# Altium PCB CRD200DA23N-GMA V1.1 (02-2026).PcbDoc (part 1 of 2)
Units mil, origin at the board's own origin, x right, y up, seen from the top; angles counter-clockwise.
Board outline 11500 x 10500 mil, 6 copper layers (Top Layer, Layer 1, Layer 2, Layer 3, Layer 4, Bottom Layer), stack 92.199 mil thick; 97 components, 36 nets, 406 pads, 60 vias.
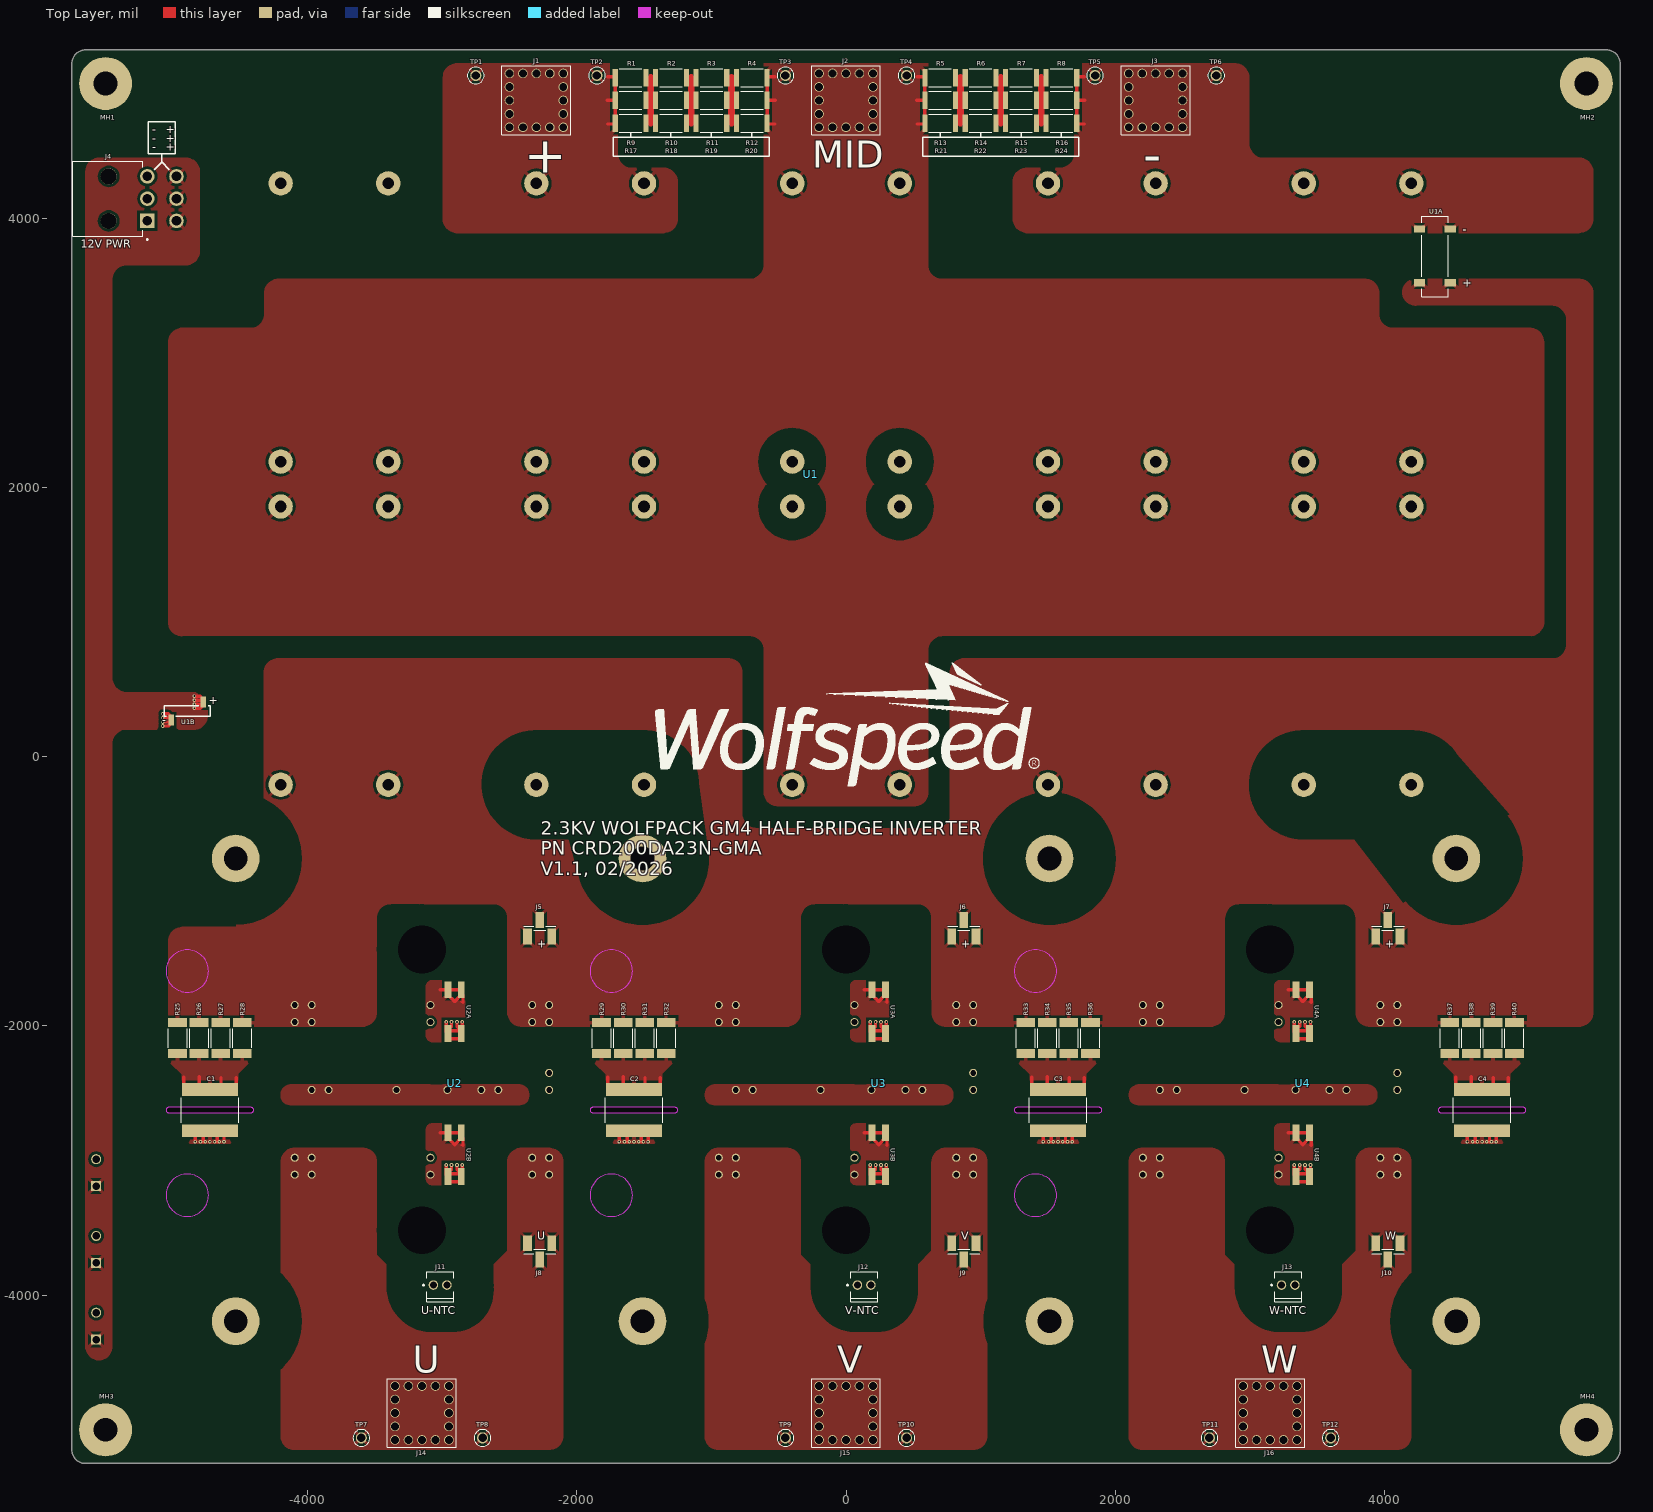
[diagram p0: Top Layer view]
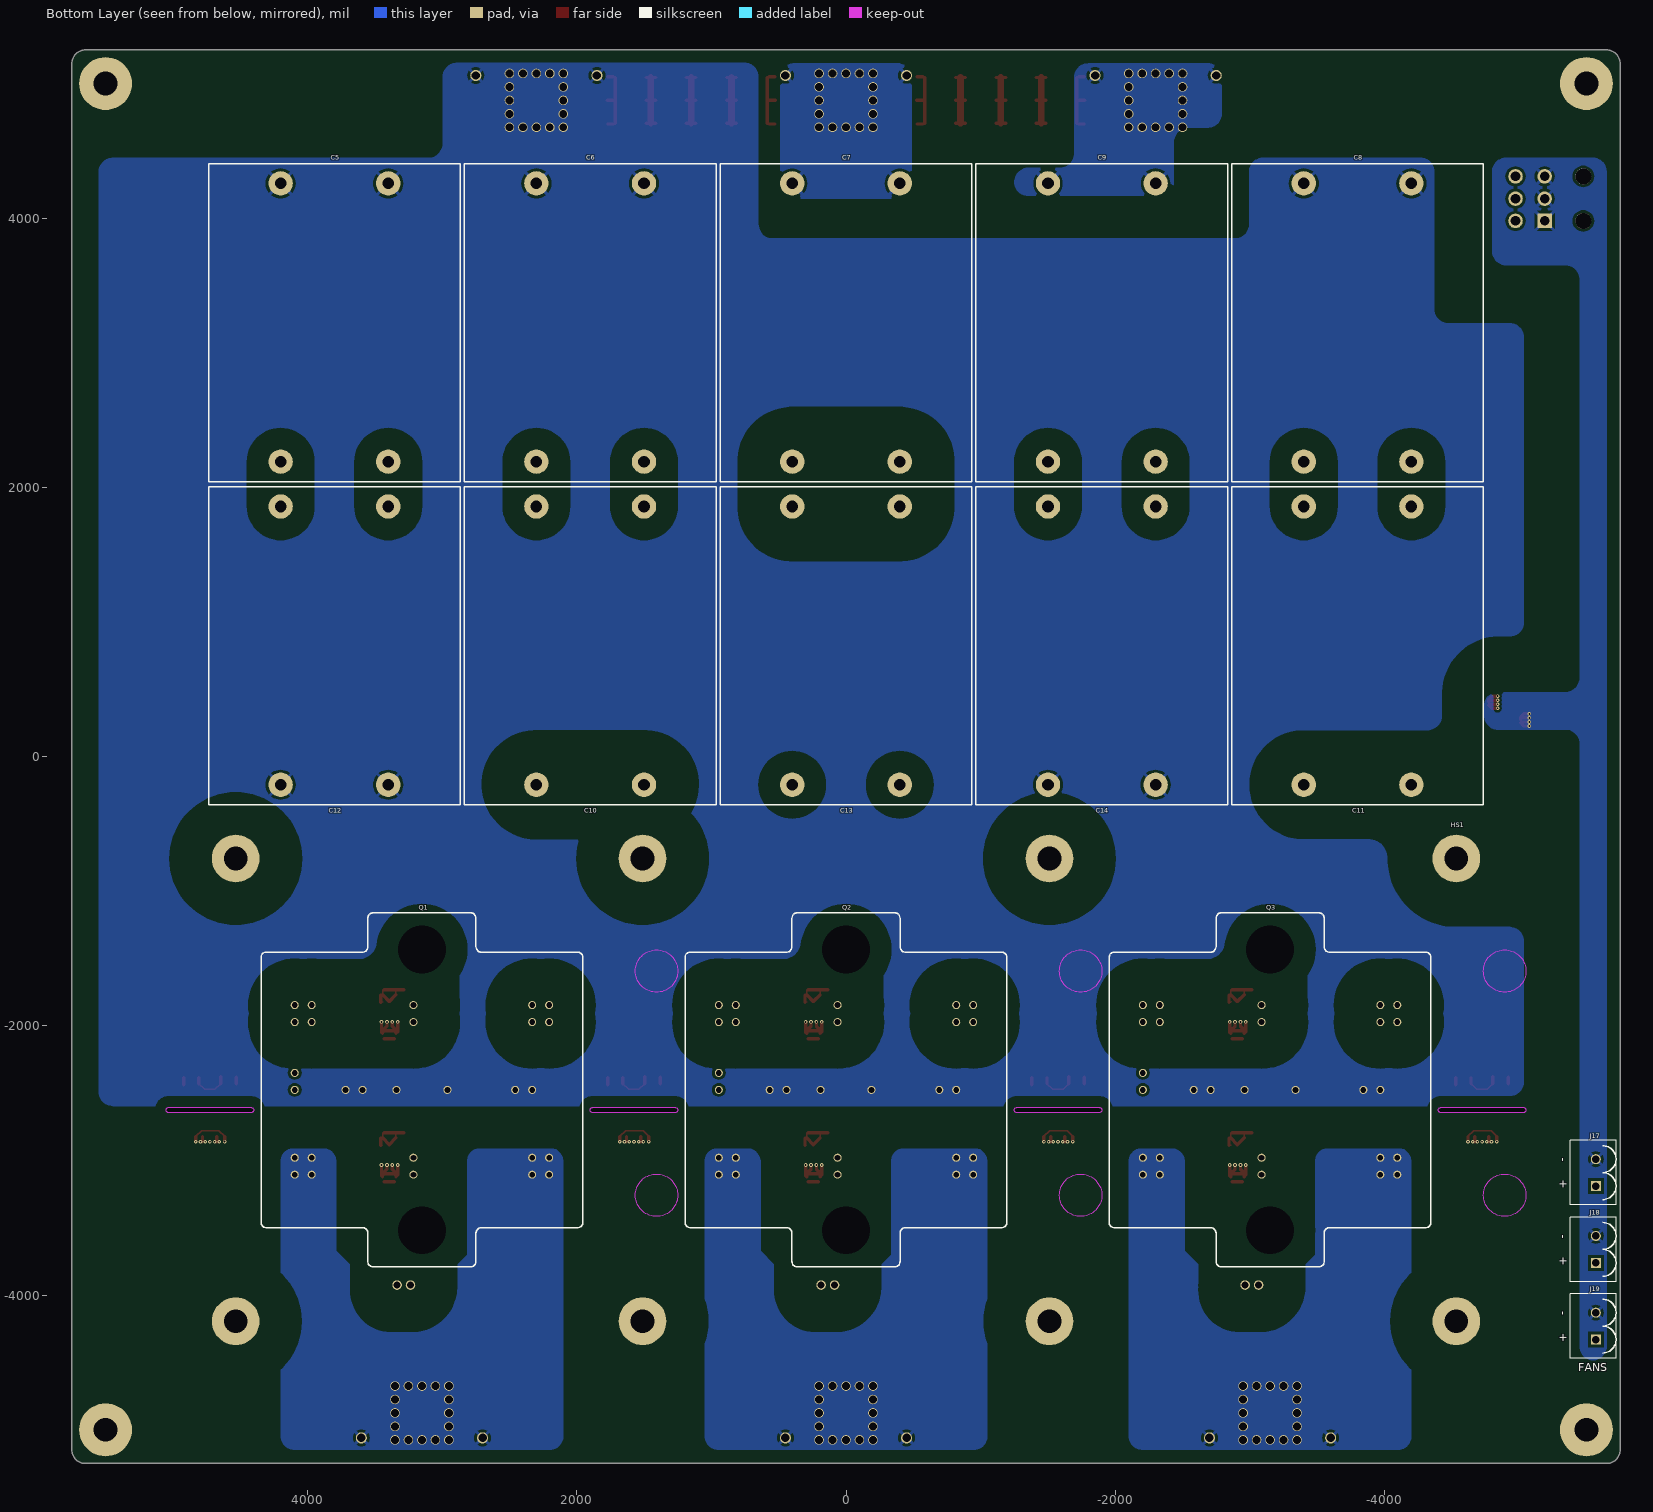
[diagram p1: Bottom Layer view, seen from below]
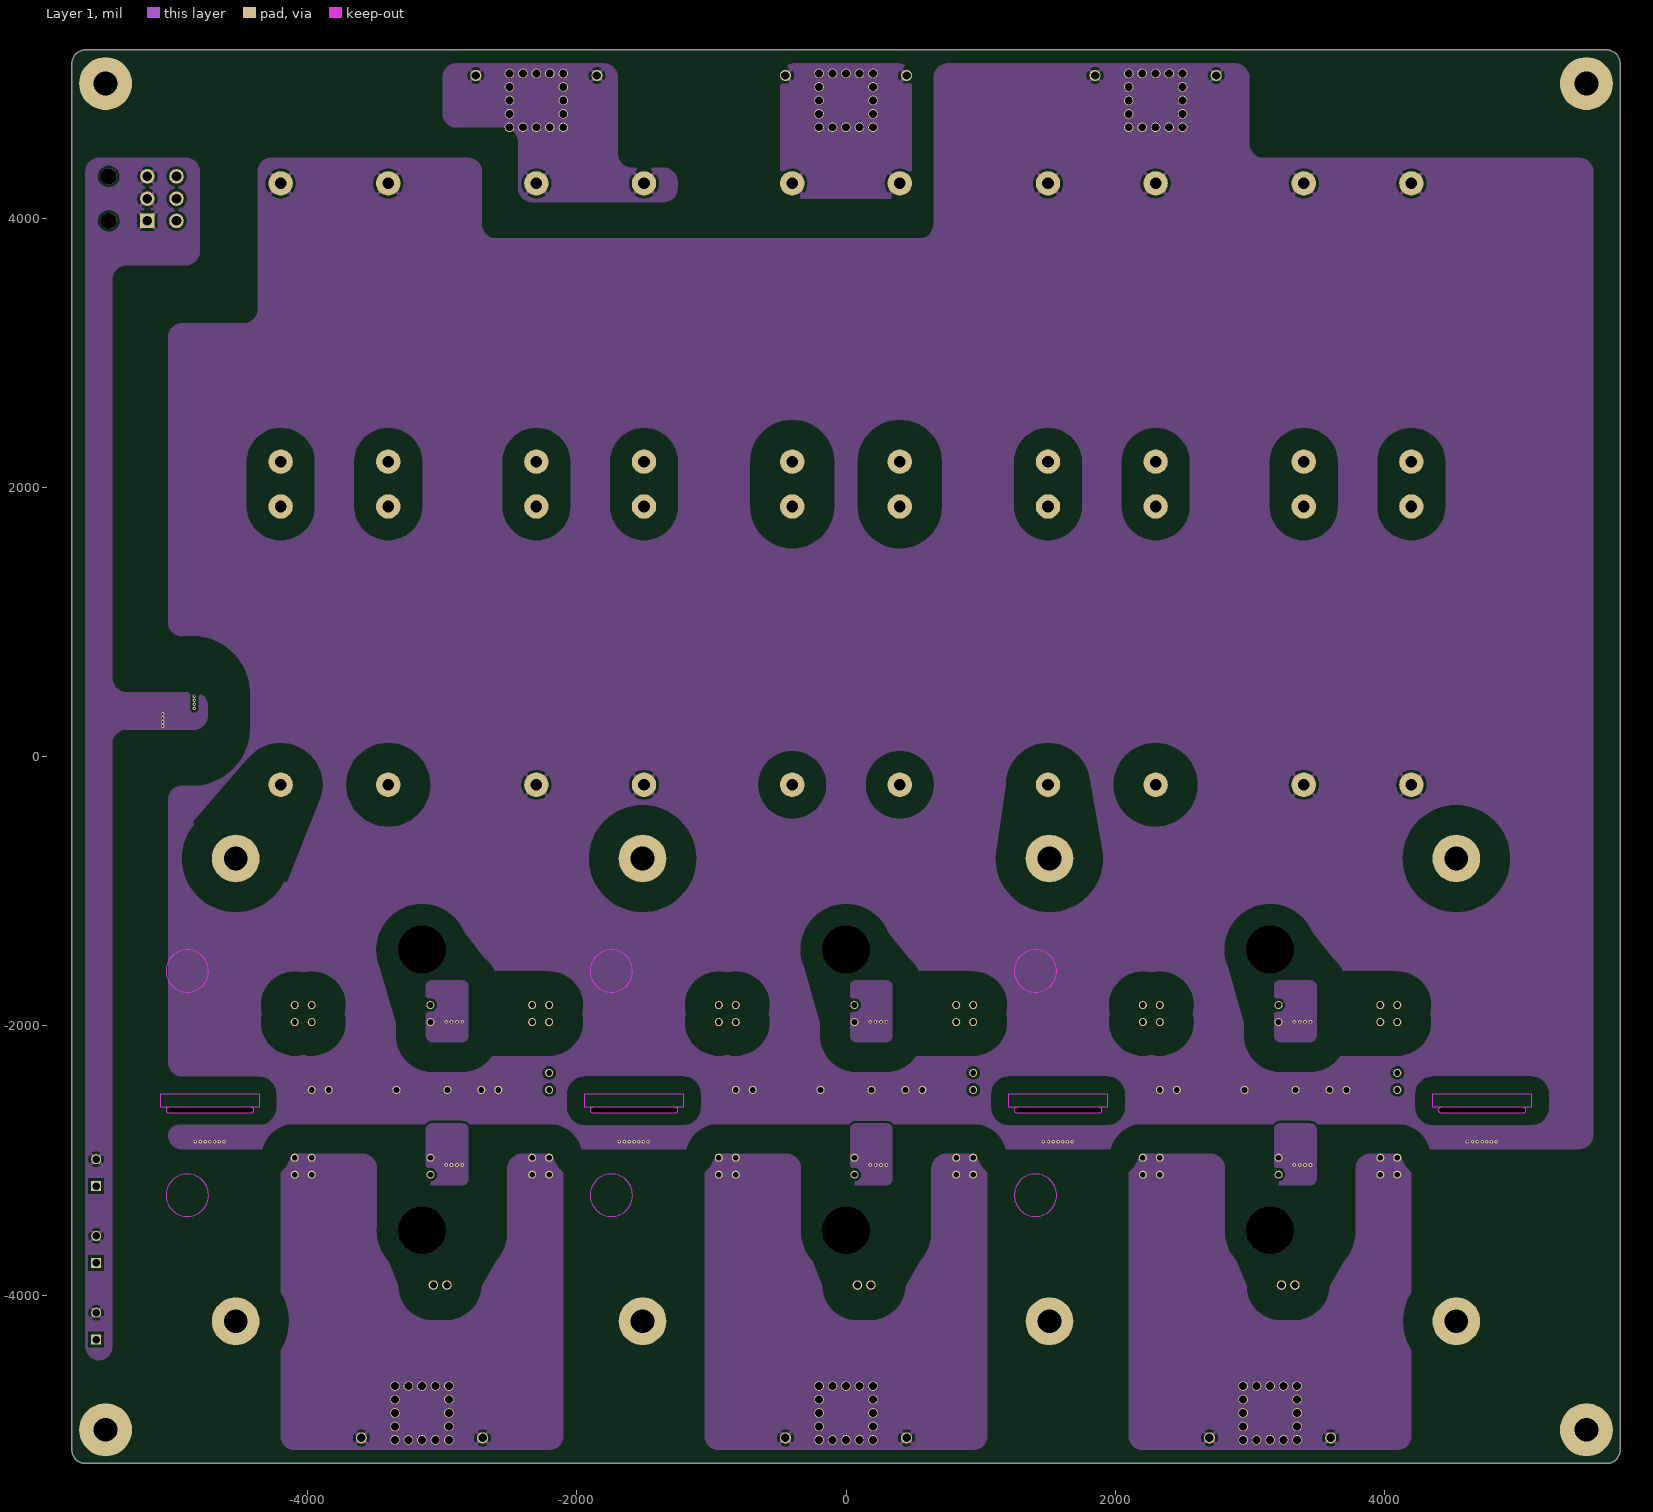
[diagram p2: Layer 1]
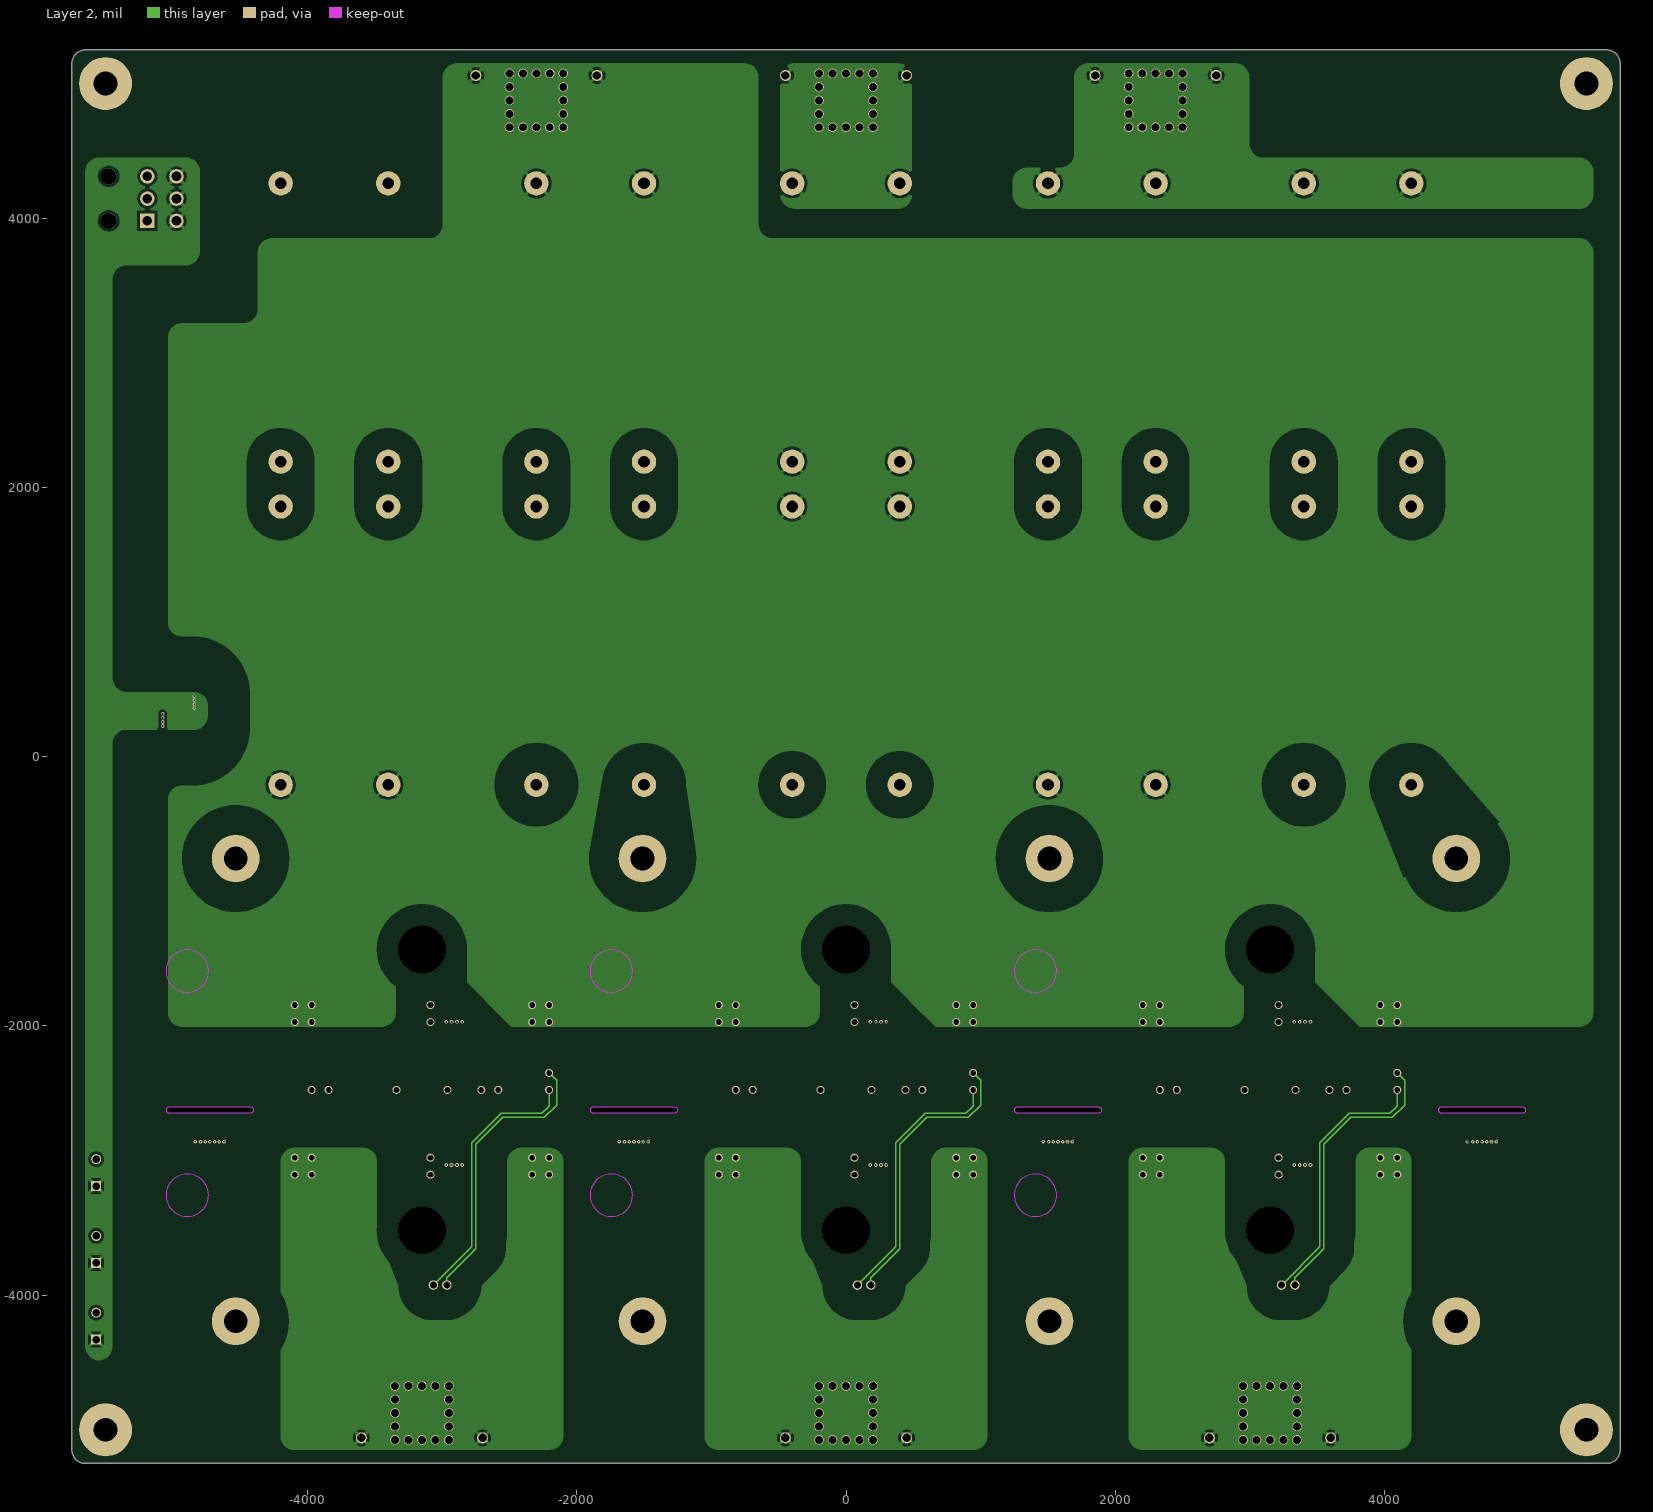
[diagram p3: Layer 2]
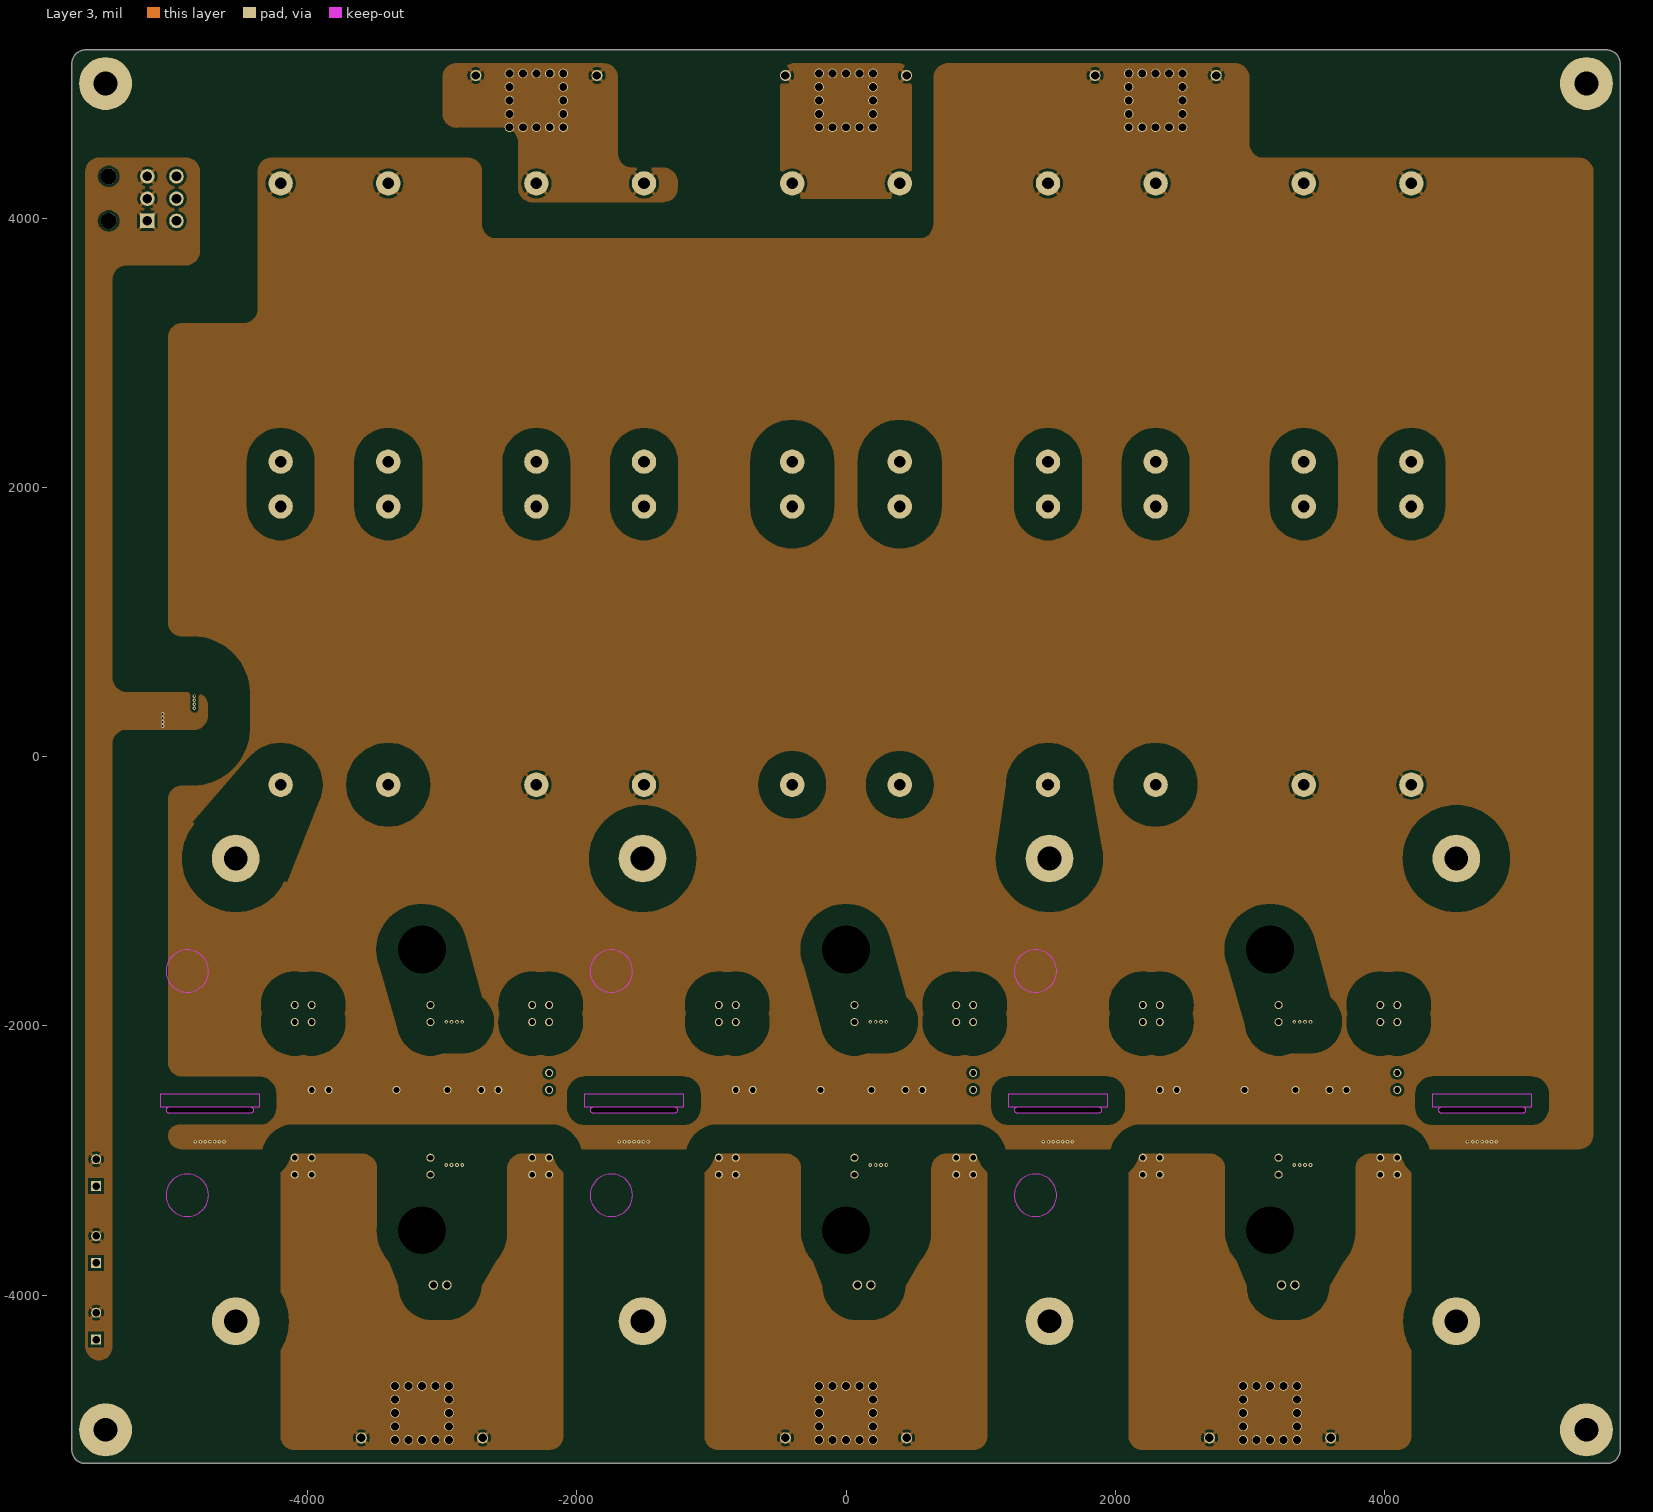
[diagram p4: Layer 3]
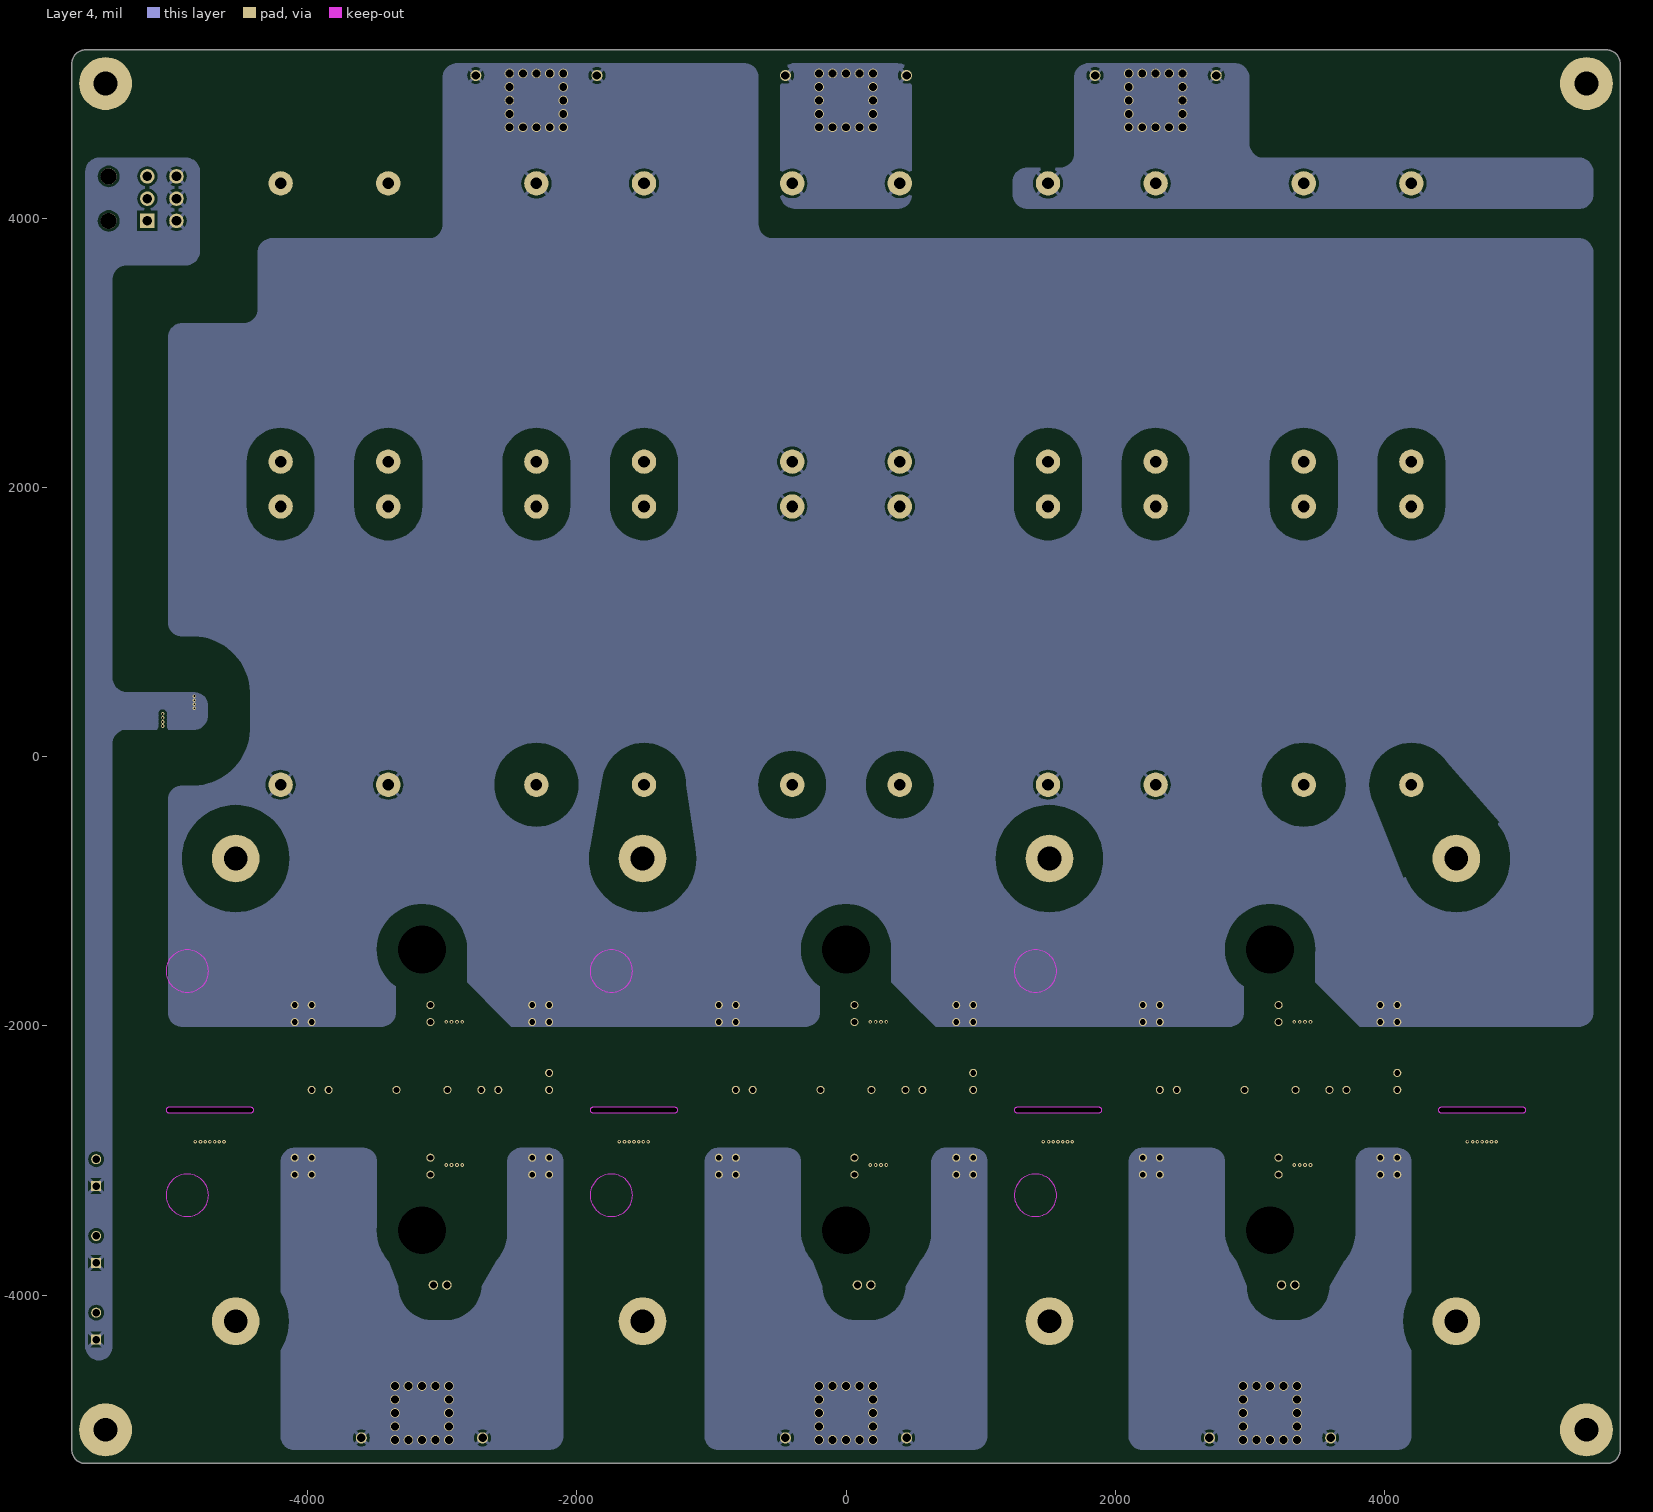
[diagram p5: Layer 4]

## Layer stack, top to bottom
Top Solder: solder mask 0.4, Solder Resist, Dk 3.5
Top Layer: signal copper 5.5118
Dielectric 2: prepreg 2.8, PP-006, Dk 4.1
Layer 1: signal copper 5.5118
Dielectric 3: prepreg 2.8, PP-006, Dk 4.1
Layer 2: signal copper 5.5118
Dielectric 1: dielectric 47.928, FR-4, Dk 4.8
Layer 3: signal copper 5.5118
Dielectric 4: prepreg 2.8, PP-006, Dk 4.1
Layer 4: signal copper 5.5118
Dielectric 5: prepreg 2.8, PP-006, Dk 4.1
Bottom Layer: signal copper 5.5118
Bottom Solder: solder mask 0.4, Solder Resist, Dk 3.5

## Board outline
-5750,-5150 -5750,5150 cw(c-5650,5150) -5650,5250 5650,5250 cw(c5650,5150) 5750,5150 5750,-5150 cw(c5650,-5150) 5650,-5250 -5650,-5250 cw(c-5650,-5150)
cut-out: -5030,-2605 ccw(c-5030,-2625) -5030,-2645 -4420,-2645 ccw(c-4420,-2625) -4420,-2605
cut-out: 4420,-2605 ccw(c4420,-2625) 4420,-2645 5030,-2645 ccw(c5030,-2625) 5030,-2605
cut-out: 1270,-2605 ccw(c1270,-2625) 1270,-2645 1880,-2645 ccw(c1880,-2625) 1880,-2605
cut-out: -1880,-2605 ccw(c-1880,-2625) -1880,-2645 -1270,-2645 ccw(c-1270,-2625) -1270,-2605

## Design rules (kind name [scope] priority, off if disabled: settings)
Clearance "DC+ to DC+" [InNetClass('DC+_CLASS') vs InNetClass('DC+_CLASS')] p1: gap=20 ignorepadtopadclearanceinfootprint=FALSE
Clearance "DC- to DC-" [InNetClass('DC-_CLASS') vs InNetClass('DC-_CLASS')] p2: gap=20 ignorepadtopadclearanceinfootprint=FALSE
Clearance "U to U" [InNetClass('U_CLASS') vs InNetClass('U_CLASS')] p3: gap=20 ignorepadtopadclearanceinfootprint=FALSE
Clearance "V to V" [InNetClass('V_CLASS') vs InNetClass('V_CLASS')] p4: gap=20 ignorepadtopadclearanceinfootprint=FALSE
Clearance "W to W" [InNetClass('W_CLASS') vs InNetClass('W_CLASS')] p5: gap=20 ignorepadtopadclearanceinfootprint=FALSE
Clearance "LV to LV" [InNetClass('LV_CLASS') vs InNetClass('LV_CLASS')] p6: gap=20 ignorepadtopadclearanceinfootprint=TRUE
Clearance "Heat Sink EXT" [OnOutside vs HasFootprint('LA HB 9 100')] p7: gap=315 ignorepadtopadclearanceinfootprint=FALSE
Clearance "Heat Sink INT" [OnMid vs HasFootprint('LA HB 9 100')] p8: gap=220 ignorepadtopadclearanceinfootprint=FALSE
Clearance "LV to Other" [InNetClass('LV_CLASS') vs Not InNetClass('LV_CLASS')] p9: gap=315 ignorepadtopadclearanceinfootprint=FALSE except(20: Arc-Hole Track-Hole SMDPad-Hole THPad-Hole Via-Hole Fill-Hole Poly-Hole Region-Hole Text-Hole)
Clearance "HS Gate-Source Creepage" [InNet('G_UHS') Or InNet('S_UHS') Or InNet('G_VHS') Or InNet('S_VHS') Or InNet('G_WHS') Or InNet('S_WHS') vs Hole] p10: gap=20 ignorepadtopadclearanceinfootprint=FALSE
Clearance MID [InNetClass('MID_CLASS')] p11: gap=160 ignorepadtopadclearanceinfootprint=FALSE
Clearance "SNUB to DC+" [InNetClass('SNUB_CLASS') vs InNetClass('DC+_CLASS')] p12: gap=160 ignorepadtopadclearanceinfootprint=FALSE
Clearance "SNUB to DC-" [InNetClass('SNUB_CLASS') vs InNetClass('DC-_CLASS')] p13: gap=210 ignorepadtopadclearanceinfootprint=FALSE
Clearance Cutout [InNet('DC-') vs IsBoardCutoutRegion] p14: gap=85 ignorepadtopadclearanceinfootprint=FALSE
Clearance Keepout [InNet('DC-') vs IsKeepOut] p15: gap=130 ignorepadtopadclearanceinfootprint=FALSE
Clearance BLD+ [InNetClass('BLD+_CLASS') vs InNetClass('DC+_CLASS') Or InNetClass('MID_CLASS') Or InNetClass('BLD+_CLASS')] p16: gap=160 ignorepadtopadclearanceinfootprint=FALSE
Clearance BLD- [InNetClass('BLD-_CLASS') vs InNetClass('DC-_CLASS') Or InNetClass('MID_CLASS') Or InNetClass('BLD-_CLASS')] p17: gap=160 ignorepadtopadclearanceinfootprint=FALSE
Clearance "External Layers" [InNetClass('All Nets') vs OnOutside] p18: gap=315 ignorepadtopadclearanceinfootprint=TRUE except(160: Arc-Hole Track-Hole SMDPad-Hole THPad-Hole Via-Hole Fill-Hole Poly-Hole Region-Hole Text-Hole)
Clearance "Internal Layers" [InNetClass('All Nets') vs OnMid] p19: gap=220 ignorepadtopadclearanceinfootprint=TRUE except(160: Arc-Hole Track-Hole SMDPad-Hole THPad-Hole Via-Hole Fill-Hole Poly-Hole Region-Hole Text-Hole)
Clearance Default [All] p20: gap=20 ignorepadtopadclearanceinfootprint=FALSE except(160: Arc-Hole Track-Hole SMDPad-Hole THPad-Hole Via-Hole Fill-Hole Poly-Hole Region-Hole Text-Hole)
Height [All] p1: minheight=0 maxheight=4000 prefheight=500
HoleSize [All] p1: absolutevalues=TRUE maxlimit=360 minlimit=1 maxpercent=80.000 minpercent=20.000
PolygonConnect "90Deg Connect" [All vs HasFootprint('FP-RMCF2512-IPC_A') Or HasFootprint('CAPC9501060_270N_KEM')] p1: connectstyle=Relief reliefconductorwidth=25 reliefentries=4 polygonreliefangle="90 Angle" airgapwidth=20
PolygonConnect "Press-Fit Connect" [All vs HasFootprint('7461059') Or HasFootprint('CAB5R0A23GM4_NOHOLE')] p2: connectstyle=Direct reliefconductorwidth=10 reliefentries=4 polygonreliefangle="90 Angle" airgapwidth=10
PolygonConnect [All] p3: thpad.connectstyle=Relief thpad.reliefconductorwidth=25 thpad.reliefentries=4 thpad.polygonreliefangle="45 Angle" thpad.airgapwidth=20 smdpad.connectstyle=Relief smdpad.reliefconductorwidth=25 smdpad.reliefentries=4 smdpad.polygonreliefangle="45 Angle" smdpad.airgapwidth=20 via.connectstyle=Direct via.reliefconductorwidth=25 via.reliefentries=4 via.polygonreliefangle="45 Angle" via.airgapwidth=20
RoutingVias [All] p1: holewidth=28 width=50 viastyle="Through Hole" minholewidth=28 minwidth=50 maxholewidth=28 maxwidth=50
SilkToSolderMaskClearance [IsPad] p1: minsilkscreentomaskgap=7.5 clearancetoexposedcopper=TRUE
SolderMaskExpansion [All] p1: expansion=4 istentingtop=FALSE
SupplyNets "Schematic Supply Nets_1" [InNet('GND')] p1: voltage=0.000
SupplyNets "Schematic Supply Nets" [InNet('+12V')] p2: voltage=0.000
Width [All] p1: maxlimit=100 minlimit=10 preferedwidth=25
27 further rules are at their usual default settings.

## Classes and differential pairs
net class SNUB_CLASS: SNB0 SNB1 SNB2 SNB3
net class BLD-_CLASS: BLD-0 BLD-1 BLD-2
net class BLD+_CLASS: BLD+0 BLD+1 BLD+2
net class LV_CLASS: +12V GND
net class W_CLASS: G_WHS S_WHS W
net class V_CLASS: G_VHS S_VHS V
net class U_CLASS: G_UHS S_UHS U
net class MID_CLASS: MID
net class DC-_CLASS: DC- G_ULS G_VLS G_WLS S_ULS S_VLS S_WLS T1U T1V T1W T2U T2V T2W
net class DC+_CLASS: DC+

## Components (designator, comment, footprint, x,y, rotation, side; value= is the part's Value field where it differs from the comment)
C1 "C3640C153JGGACAUTO" CAPC9501060_270N_KEM -4725,-2625 r270 top value=15nF (schematic designator C12)
C2 "C3640C153JGGACAUTO" CAPC9501060_270N_KEM -1575,-2625 r270 top value=15nF (schematic designator C11)
C3 "C3640C153JGGACAUTO" CAPC9501060_270N_KEM 1575,-2625 r270 top value=15nF (schematic designator C14)
C4 "C3640C153JGGACAUTO" CAPC9501060_270N_KEM 4725,-2625 r270 top value=15nF (schematic designator C13)
C5 "C4AQQEW5650A3BJ" C4AQNEW5650M3BJ 3800,3225 r90 bottom value=65µF (schematic designator C7)
C6 "C4AQQEW5650A3BJ" C4AQNEW5650M3BJ 1900,3225 r90 bottom value=65µF (schematic designator C10)
C7 "C4AQQEW5650A3BJ" C4AQNEW5650M3BJ 0,3225 r90 bottom value=65µF (schematic designator C1)
C8 "C4AQQEW5650A3BJ" C4AQNEW5650M3BJ -3800,3225 r90 bottom value=65µF (schematic designator C5)
C9 "C4AQQEW5650A3BJ" C4AQNEW5650M3BJ -1900,3225 r270 bottom value=65µF (schematic designator C3)
C10 "C4AQQEW5650A3BJ" C4AQNEW5650M3BJ 1900,825 r90 bottom value=65µF (schematic designator C4)
C11 "C4AQQEW5650A3BJ" C4AQNEW5650M3BJ -3800,825 r90 bottom value=65µF (schematic designator C9)
C12 "C4AQQEW5650A3BJ" C4AQNEW5650M3BJ 3800,825 r270 bottom value=65µF (schematic designator C6)
C13 "C4AQQEW5650A3BJ" C4AQNEW5650M3BJ 0,825 r270 bottom value=65µF (schematic designator C2)
C14 "C4AQQEW5650A3BJ" C4AQNEW5650M3BJ -1900,825 r270 bottom value=65µF (schematic designator C8)
HS1 "LA HB 9 100 12" "LA HB 9 100" 0,-2475 r180 bottom value=N/A
J1 "7461059" 7461059 -2300,4875 r0 top value=N/A
J2 "7461059" 7461059 0,4875 r0 top value=N/A (schematic designator J6)
J3 "7461059" 7461059 2300,4875 r0 top value=N/A (schematic designator J5)
J4 "0039301062" FP-39-30-1062-MFG -5485,4145 r270 top value=N/A (schematic designator J16)
J5 "4928" KEYSTONE_4928 -2275,-1275 r180 top value=N/A (schematic designator J10)
J6 "4928" KEYSTONE_4928 875,-1275 r180 top value=N/A (schematic designator J11)
J7 "4928" KEYSTONE_4928 4025,-1275 r180 top value=N/A (schematic designator J12)
J8 "4928" KEYSTONE_4928 -2275,-3675 r0 top value=N/A (schematic designator J13)
J9 "4928" KEYSTONE_4928 875,-3675 r0 top value=N/A (schematic designator J14)
J10 "4928" KEYSTONE_4928 4025,-3675 r0 top value=N/A (schematic designator J15)
J11 "640456-2" TECO-640456-2_V -3015,-3925 r180 top value=N/A (schematic designator J7)
J12 "640456-2" TECO-640456-2_V 135,-3925 r180 top value=N/A (schematic designator J8)
J13 "640456-2" TECO-640456-2_V 3285,-3925 r180 top value=N/A (schematic designator J9)
J14 "7461059" 7461059 -3150,-4875 r0 top value=N/A (schematic designator J2)
J15 "7461059" 7461059 0,-4875 r0 top value=N/A (schematic designator J3)
J16 "7461059" 7461059 3150,-4875 r0 top value=N/A (schematic designator J4)
J17 "1755736" 1755736 -5570,-3090 r90 bottom value=N/A (schematic designator J19)
J18 "1755736" 1755736 -5570,-3660 r90 bottom value=N/A
J19 "1755736" 1755736 -5570,-4230 r90 bottom value=N/A (schematic designator J17)
MH1 "MH_M4_P" MH_M4_P -5500,5000 r0 top value=N/A
MH2 "MH_M4_P" MH_M4_P 5500,5000 r0 top value=N/A
MH3 "MH_M4_P" MH_M4_P -5500,-5000 r0 top value=N/A
MH4 "MH_M4_P" MH_M4_P 5500,-5000 r0 top value=N/A
Q1 "CAB5R0A23GM4T" CAB5R0A23GM4_NOHOLE 3150,-2475 r180 bottom value=N/A (schematic designator Q3)
Q2 "CAB5R0A23GM4T" CAB5R0A23GM4_NOHOLE 0,-2475 r180 bottom locked value=N/A
Q3 "CAB5R0A23GM4T" CAB5R0A23GM4_NOHOLE -3150,-2475 r180 bottom locked value=N/A (schematic designator Q1)
R1 "CRGP2512F220K" FP-CRGP2512-IPC_C -1600,5045 r180 top value=220kΩ
R2 "CRGP2512F220K" FP-CRGP2512-IPC_C -1300,5045 r180 top value=220kΩ (schematic designator R4)
R3 "CRGP2512F220K" FP-CRGP2512-IPC_C -1000,5045 r180 top value=220kΩ (schematic designator R7)
R4 "CRGP2512F220K" FP-CRGP2512-IPC_C -700,5045 r180 top value=220kΩ (schematic designator R10)
R5 "CRGP2512F220K" FP-CRGP2512-IPC_C 700,5045 r180 top value=220kΩ (schematic designator R15)
R6 "CRGP2512F220K" FP-CRGP2512-IPC_C 1000,5045 r180 top value=220kΩ (schematic designator R16)
R7 "CRGP2512F220K" FP-CRGP2512-IPC_C 1300,5045 r180 top value=220kΩ (schematic designator R21)
R8 "CRGP2512F220K" FP-CRGP2512-IPC_C 1600,5045 r180 top value=220kΩ (schematic designator R22)
R9 "CRGP2512F220K" FP-CRGP2512-IPC_C -1600,4875 r180 top value=220kΩ (schematic designator R2)
R10 "CRGP2512F220K" FP-CRGP2512-IPC_C -1300,4875 r180 top value=220kΩ (schematic designator R5)
R11 "CRGP2512F220K" FP-CRGP2512-IPC_C -1000,4875 r180 top value=220kΩ (schematic designator R8)
R12 "CRGP2512F220K" FP-CRGP2512-IPC_C -700,4875 r180 top value=220kΩ (schematic designator R11)
R13 "CRGP2512F220K" FP-CRGP2512-IPC_C 700,4875 r180 top value=220kΩ (schematic designator R14)
R14 "CRGP2512F220K" FP-CRGP2512-IPC_C 1000,4875 r180 top value=220kΩ (schematic designator R17)
R15 "CRGP2512F220K" FP-CRGP2512-IPC_C 1300,4875 r180 top value=220kΩ (schematic designator R19)
R16 "CRGP2512F220K" FP-CRGP2512-IPC_C 1600,4875 r180 top value=220kΩ (schematic designator R23)
R17 "CRGP2512F220K" FP-CRGP2512-IPC_C -1600,4705 r180 top value=220kΩ (schematic designator R3)
R18 "CRGP2512F220K" FP-CRGP2512-IPC_C -1300,4705 r180 top value=220kΩ (schematic designator R6)
R19 "CRGP2512F220K" FP-CRGP2512-IPC_C -1000,4705 r180 top value=220kΩ (schematic designator R9)
R20 "CRGP2512F220K" FP-CRGP2512-IPC_C -700,4705 r180 top value=220kΩ (schematic designator R12)
R21 "CRGP2512F220K" FP-CRGP2512-IPC_C 700,4705 r180 top value=220kΩ (schematic designator R13)
R22 "CRGP2512F220K" FP-CRGP2512-IPC_C 1000,4705 r180 top value=220kΩ (schematic designator R18)
R23 "CRGP2512F220K" FP-CRGP2512-IPC_C 1300,4705 r180 top value=220kΩ (schematic designator R20)
R24 "CRGP2512F220K" FP-CRGP2512-IPC_C 1600,4705 r180 top value=220kΩ
R25 "CRCW251210R0FKEGHP" FP-RMCF2512-IPC_A -4965,-2090 r90 top value=10Ω (schematic designator R29)
R26 "CRCW251210R0FKEGHP" FP-RMCF2512-IPC_A -4805,-2090 r90 top value=10Ω (schematic designator R30)
R27 "CRCW251210R0FKEGHP" FP-RMCF2512-IPC_A -4645,-2090 r90 top value=10Ω (schematic designator R31)
R28 "CRCW251210R0FKEGHP" FP-RMCF2512-IPC_A -4485,-2090 r90 top value=10Ω (schematic designator R32)
R29 "CRCW251210R0FKEGHP" FP-RMCF2512-IPC_A -1815,-2090 r90 top value=10Ω (schematic designator R25)
R30 "CRCW251210R0FKEGHP" FP-RMCF2512-IPC_A -1655,-2090 r90 top value=10Ω (schematic designator R26)
R31 "CRCW251210R0FKEGHP" FP-RMCF2512-IPC_A -1495,-2090 r90 top value=10Ω (schematic designator R27)
R32 "CRCW251210R0FKEGHP" FP-RMCF2512-IPC_A -1335,-2090 r90 top value=10Ω (schematic designator R28)
R33 "CRCW251210R0FKEGHP" FP-RMCF2512-IPC_A 1335,-2090 r90 top value=10Ω (schematic designator R37)
R34 "CRCW251210R0FKEGHP" FP-RMCF2512-IPC_A 1495,-2090 r90 top value=10Ω (schematic designator R38)
R35 "CRCW251210R0FKEGHP" FP-RMCF2512-IPC_A 1655,-2090 r90 top value=10Ω (schematic designator R39)
R36 "CRCW251210R0FKEGHP" FP-RMCF2512-IPC_A 1815,-2090 r90 top value=10Ω (schematic designator R40)
R37 "CRCW251210R0FKEGHP" FP-RMCF2512-IPC_A 4485,-2090 r90 top value=10Ω (schematic designator R33)
R38 "CRCW251210R0FKEGHP" FP-RMCF2512-IPC_A 4645,-2090 r90 top value=10Ω (schematic designator R34)
R39 "CRCW251210R0FKEGHP" FP-RMCF2512-IPC_A 4805,-2090 r90 top value=10Ω (schematic designator R35)
R40 "CRCW251210R0FKEGHP" FP-RMCF2512-IPC_A 4965,-2090 r90 top value=10Ω (schematic designator R36)
TP1 "5010" KSTN-5010_V -2750,5060 r0 top value=RED (schematic designator TP2)
TP2 "5010" KSTN-5010_V -1850,5060 r0 top value=RED (schematic designator TP1)
TP3 "5012" KSTN-5012_V -450,5060 r0 top value=WHITE (schematic designator TP5)
TP4 "5012" KSTN-5012_V 450,5060 r0 top value=WHITE (schematic designator TP6)
TP5 "5011" KSTN-5011_V 1850,5060 r0 top value=BLACK (schematic designator TP3)
TP6 "5011" KSTN-5011_V 2750,5060 r0 top value=BLACK (schematic designator TP4)
TP7 "5014" KSTN-5014_V -3600,-5060 r0 top value=YELLOW
TP8 "5014" KSTN-5014_V -2700,-5060 r0 top value=YELLOW
TP9 "5014" KSTN-5014_V -450,-5060 r0 top value=YELLOW
TP10 "5014" KSTN-5014_V 450,-5060 r0 top value=YELLOW
TP11 "5014" KSTN-5014_V 2700,-5060 r0 top value=YELLOW
TP12 "5014" KSTN-5014_V 3600,-5060 r0 top value=YELLOW
U1 "XM Controller" "XM CONTROLLER" 0,2200 r0 top value=N/A (schematic designator U4)
U2 "CGD1700HB2M-UNA" CGD1700HB2P-UNA_NOHOLE -3875,-2425 r0 top locked value=N/A (schematic designator U1)
U3 "CGD1700HB2M-UNA" CGD1700HB2P-UNA_NOHOLE -725,-2425 r0 top locked value=N/A (schematic designator U2)
U4 "CGD1700HB2M-UNA" CGD1700HB2P-UNA_NOHOLE 2425,-2425 r0 top value=N/A (schematic designator U3)

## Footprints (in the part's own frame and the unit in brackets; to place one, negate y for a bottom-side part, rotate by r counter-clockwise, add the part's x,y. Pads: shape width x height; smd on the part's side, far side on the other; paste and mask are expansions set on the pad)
1755736 [mm] "THD, 2-Leads, Body 12.16x8.6mm, Pitch 5.08mm"
  rect 1.9x1.9 hole 1.4: 1(-2.54,0)
  round 1.9 hole 1.4: 2(2.54,0)
  silkscreen extent -6.08,-3.81 6.08,4.79, body extent -6.08,-3.8 6.16,4.87, height 12
7461059 [mm] "M6, thr 13.5mm"
  round 1.8 hole 1.475: 1(-5.08,-5.08) 1(-5.08,-2.54) 1(-5.08,0) 1(-5.08,2.54) 1(-5.08,5.08) 1(-2.54,-5.08) 1(-2.54,5.08) 1(0,-5.08) 1(0,5.08) 1(2.54,-5.08) 1(2.54,5.08) 1(5.08,-5.08) 1(5.08,-2.54) 1(5.08,0) 1(5.08,2.54) 1(5.08,5.08)
  silkscreen extent -6.5,-6.5 6.5,6.5, body extent -6.5,-6.5 6.5,6.5, height 13.5
C4AQNEW5650M3BJ [mm]
  round 4.6 hole 2.2: 1A(-26.25,10.15) 1B(-26.25,-10.15) 2A(26.25,10.15) 2B(26.25,-10.15)
  silkscreen extent -30,-23.75 30,23.75, body extent -29.15,-22.81 29.15,22.7, height 65.3
CAB5R0A23GM4_NOHOLE [mm] "Wolfpack GM Half-Bridge 2.3kV footprint"
  round 1.524 hole 1.09: AC_1(-24,-12.8) AC_2(-24,-16) AC_3(-20.8,-12.8) AC_4(-20.8,-16) AC_5(20.8,-12.8) AC_6(20.8,-16) AC_7(24,-12.8) AC_8(24,-16) DC+_1(-24,16) DC+_2(-24,12.8) DC+_3(-20.8,16) DC+_4(-20.8,12.8) DC+_5(20.8,16) DC+_6(20.8,12.8) DC+_7(24,16) DC+_8(24,12.8) DC-_1(20.8,0) DC-_2(17.6,0) DC-_3(-4.8,0) DC-_4(4.8,0) DC-_5(-11.2,0) DC-_6(-14.4,0) G1(-1.6,16) G2(-1.6,-16) S1(-1.6,12.8) S2(-1.6,-12.8) T1(-24,3.2) T2(-24,0)
  round 0.1 hole 9 unplated: ""(0,-26.5) ""(0,26.5)
  silkscreen extent -30.35,-33.4 30.35,33.4, body extent -28.35,-31.39 28.35,31.41, height 17.35
CAPC9501060_270N_KEM [mil]
  rect 95.5x417.32 smd paste+0 mask+0: 1(-153.26,0) 2(153.26,0)
  silkscreen extent -93,-214 93,214, body extent -187,-209 187,209, height 106
CGD1700HB2P-UNA_NOHOLE [mil] "Wolfpack FM/GM Gate Driver"
  rect 50x125 smd: 1A(917.84,369) 1B(917.84,-694) 2A(917.84,694) 2B(917.84,-369) 3A(1017.84,369) 3B(1017.84,-694) 4A(1017.84,694) 4B(1017.84,-369)
  Multi-Layer keep-out region: -1017.84,990 -1017.84,990 -1031.56,989.4 -1045.18,987.61 -1058.59,984.63 -1071.7,980.5 -1084.39,975.25 -1096.57,968.9 -1108.16,961.52 -1119.06,953.16 -1129.19,943.88 -1138.47,933.75 -1146.84,922.85 -1154.22,911.26 -1160.56,899.07 -1165.82,886.38 -1169.95,873.28 -1172.92,859.87 -1174.72,846.25 -1175.32,832.52 -1174.72,818.79 -1172.92,805.17 -1169.95,791.76 -1165.82,778.66 -1160.56,765.97 -1154.22,753.78 -1146.84,742.19 -1138.47,731.29 -1129.19,721.16 -1119.06,711.88 -1108.16,703.52 -1096.57,696.14 -1084.39,689.79 -1071.7,684.54 -1058.59,680.41 -1045.18,677.43 -1031.56,675.64 -1017.84,675.04 -1017.84,675.04 -1004.11,675.64 -990.49,677.43 -977.08,680.41 -963.97,684.54 -951.28,689.79 -939.09,696.14 -927.51,703.52 -916.61,711.88 -906.48,721.16 -897.2,731.29 -888.83,742.19 -881.45,753.78 -875.11,765.97 -869.85,778.66 -865.72,791.76 -862.75,805.17 -860.95,818.79 -860.36,832.52 -860.95,846.25 -862.75,859.87 -865.72,873.28 -869.85,886.38 -875.11,899.07 -881.45,911.26 -888.83,922.85 -897.2,933.75 -906.48,943.88 -916.61,953.16 -927.51,961.52 -939.09,968.9 -951.28,975.25 -963.97,980.5 -977.08,984.63 -990.49,987.61 -1004.11,989.4 -1017.84,990
  Multi-Layer keep-out region: -1017.84,-675.04 -1017.84,-675.04 -1031.56,-675.64 -1045.18,-677.43 -1058.59,-680.41 -1071.7,-684.54 -1084.39,-689.79 -1096.57,-696.14 -1108.16,-703.52 -1119.06,-711.88 -1129.19,-721.16 -1138.47,-731.29 -1146.84,-742.19 -1154.22,-753.78 -1160.56,-765.97 -1165.82,-778.66 -1169.95,-791.76 -1172.92,-805.17 -1174.72,-818.79 -1175.32,-832.52 -1174.72,-846.25 -1172.92,-859.87 -1169.95,-873.28 -1165.82,-886.38 -1160.56,-899.07 -1154.22,-911.26 -1146.84,-922.85 -1138.47,-933.75 -1129.19,-943.88 -1119.06,-953.16 -1108.16,-961.52 -1096.57,-968.9 -1084.39,-975.25 -1071.7,-980.5 -1058.59,-984.63 -1045.18,-987.61 -1031.56,-989.4 -1017.84,-990 -1017.84,-990 -1004.11,-989.4 -990.49,-987.61 -977.08,-984.63 -963.97,-980.5 -951.28,-975.25 -939.09,-968.9 -927.51,-961.52 -916.61,-953.16 -906.48,-943.88 -897.2,-933.75 -888.83,-922.85 -881.45,-911.26 -875.11,-899.07 -869.85,-886.38 -865.72,-873.28 -862.75,-859.87 -860.95,-846.25 -860.36,-832.52 -860.95,-818.79 -862.75,-805.17 -865.72,-791.76 -869.85,-778.66 -875.11,-765.97 -881.45,-753.78 -888.83,-742.19 -897.2,-731.29 -906.48,-721.16 -916.61,-711.88 -927.51,-703.52 -939.09,-696.14 -951.28,-689.79 -963.97,-684.54 -977.08,-680.41 -990.49,-677.43 -1004.11,-675.64 -1017.84,-675.04
  body extent -1200,-1291 1179,1000, height 1202
FP-39-30-1062-MFG [mm]
  rect 2.75x2.75 hole 1.8 paste-2539.97 mask+0: 1(4.2,7.5)
  round 2.75 hole 1.8 paste-2539.97 mask+0: 2(0,7.5) 3(-4.2,7.5) 4(4.2,13) 5(0,13) 6(-4.2,13)
  round 3 hole 3 unplated paste-2539.97 mask+0: ""(-4.2,0.2) ""(4.2,0.2)
  silkscreen extent -7.09,-6.59 7.81,7.63, body extent -7.19,-6.69 7.19,14.48, height 0.25
FP-CRGP2512-IPC_C [mil]
  rect 37.72x130.17 smd paste+0 mask+0: 1(-114.25,0) 2(114.25,0)
  silkscreen extent -84,-67 84,67, body extent -137,-71 137,71, height 10
FP-RMCF2512-IPC_A [mil]
  rect 67.1x139.96 smd paste+0 mask+0: 1(-116.18,0) 2(116.18,0)
  silkscreen extent -71,-70 71,70, body extent -169,-90 169,90, height 10
KEYSTONE_4928 [mm]
  rect 1.65x3 smd: 1(2.285,1.55) 2(0,-1.55) 3(-2.285,1.55)
  silkscreen extent -3.05,-0.41 3.05,0.41, body extent -3.05,-2.92 3.05,2.92, height 10.52
KSTN-5010_V [mm] "Test Point, Dia 3.17mm"
  round 2.1 hole 1.6: 1(0,0)
  silkscreen extent -1.59,-1.58 1.59,1.58, body extent -1.59,-1.59 1.59,1.59, height 8.13
KSTN-5011_V [mm] "Test Point, Dia 3.17mm"
  round 2.1 hole 1.6: 1(0,0)
  silkscreen extent -1.59,-1.58 1.59,1.58, body extent -1.59,-1.59 1.59,1.59, height 8.13
KSTN-5012_V [mm] "Test Point, Dia 3.17mm"
  round 2.1 hole 1.6: 1(0,0)
  silkscreen extent -1.59,-1.58 1.59,1.58, body extent -1.59,-1.59 1.59,1.59, height 8.13
KSTN-5014_V [mm] "Test Point, Dia 3.17mm"
  round 2.1 hole 1.6: 1(0,0)
  silkscreen extent -1.59,-1.58 1.59,1.58, body extent -1.59,-1.59 1.59,1.59, height 8.13
"LA HB 9 100" [mm]
  round 9 hole 4.5: 1(115.15,43.65) 2(38.38,43.65) 3(-38.38,43.65) 4(-115.15,43.65) 5(-115.15,-43.65) 6(-38.38,-43.65) 7(38.38,-43.65) 8(115.15,-43.65)
  body extent -121.25,-88.53 121.75,49.48, height 2.75
MH_M4_P [mm] "M4 plated mounting hole"
  round 10 hole 4.5: 1(0,0)
  body extent -4.62,-4 4.62,4, height 15
TECO-640456-2_V [mm] "HDR, 2-Leads, Body 5.715x5.08mm, Pitch 2.54mm"
  round 1.8 hole 1.3: 1(1.27,0) 2(-1.27,0)
  silkscreen extent -2.54,-2.54 3.26,3.18, body extent -2.54,-2.67 2.54,3.17, height 10.09
"XM CONTROLLER" [mm]
  rect 2.16x1.4 smd: 1(108.205,43.688) 2(114.045,43.688) 5(108.205,33.528) 6(114.045,33.528)
  rect 1.016x2.085 smd: 11(-127.282,-48.921) 14(-121.282,-45.567)
  silkscreen extent -128.6,-48.26 113.66,46.11, body extent -141.04,-55.2 135,50.8, height 24.54

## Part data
C1 C2 C3 C4: "CAP CER 0.015UF 2KV C0G/NP0 3640", Case/Package=3640, Manufacturer=KEMET, Voltage=2kV
C5 C6 C7 C8 C9 C10 C11 C12 C13 C14: "CAP FILM 65UF 5% 1.1KVDC RAD", Case/Package=RADIAL, Manufacturer=KEMET, Voltage=1.1kV
HS1: "HEATSINK EXTRUSION 100MM", Case/Package=N/A, Manufacturer=FISCHER
J1 J2 J3 J14 J15 J16: "TERM REDCUBE M6 16PIN PCB", Case/Package=N/A, Current Rating=240A, Manufacturer=WURTH, Max Operating Temperature=150°C, Min Operating Temperature=-55°C
J4: "CONN HEADER R/A 6POS 4.2MM", Case/Package=N/A, Manufacturer=MOLEX
J5 J6 J7 J8 J9 J10: "QUICK FIT TERMINAL .240\"", Case/Package=N/A, Manufacturer=KEYSTONE
J11 J12 J13: library part CMP-2000-05417-1, "CONN HEADER VERT 2POS 2.54MM", Case/Package=N/A, Color=White, Current, Rating="5 /  / A", Flammability Rating=UL94V-0, Manufacturer=TE, Temperature, Operating="-55to+105 /  / degC", Voltage, Rating="250 /  / V"
J17 J18 J19: "TERM BLOCK HDR 2POS VERT 5.08MM", Case/Package=N/A, Colour=Green, Manufacturer="PHOENIX CONTACT", Supplier Part Number 1=1896199
MH1 MH2 MH3 MH4: "PLASTIC SPACER STUD METRIC THREA", Case/Package=N/A, Manufacturer=WURTH, Manufacturer Part Number=971500485
Q1 Q2 Q3: "MOSFET 2N-CH 2300V 200A", Case/Package=GM, Manufacturer=WOLFSPEED
R1 R2 R3 R4 R5 R6 R7 R8 R9 R10 R11 R12 R13 R14 R15 R16 R17 R18 R19 R20 R21 R22 R23 R24: "RES 220K OHM 1% 2W 2512", Ambient Temperature Range High=+70°C, Case/Package=2512, Manufacturer=TE, Power Rating=2W, Resistance=220kΩ, Temperature="-55°C to +155°C", Temperature Coefficient=±100ppm/°C, Temperature Range High=+155°C, Temperature Range Low=-55°C, Tolerance=0.01, Voltage Rating=500V
R25 R26 R27 R28 R29 R30 R31 R32 R33 R34 R35 R36 R37 R38 R39 R40: "RES SMD 10 OHM 1% 1.5W 2512", Case/Package=2512, Manufacturer="VISHAY DALE", Power=1.5W
TP1 TP2: library part CMP-1672-00002-4, "PC TEST POINT MULTIPURPOSE RED", Case/Package=N/A, Colour=Red, Manufacturer=KEYSTONE, Package Quantity=100
TP3 TP4: library part CMP-1672-00004-4, "PC TEST POINT MULTIPURPOSE WHITE", Case/Package=N/A, Manufacturer=KEYSTONE, Package Quantity=100
TP5 TP6: library part CMP-1672-00003-4, "PC TEST POINT MULTIPURPOSE BLACK", Case/Package=N/A, Colour=Black, Manufacturer=KEYSTONE, Package Quantity=100
TP7 TP8 TP9 TP10 TP11 TP12: library part CMP-1672-00006-4, "PC TEST POINT MULTIPURPOSE YELLOW", Case/Package=N/A, Manufacturer=KEYSTONE, Package Quantity=100
U1: "CTRL BRD - XM3 EVAL BRD", Case/Package=N/A, Manufacturer=WOLFSPEED, Manufacturer Part Number=CRD300DA12E-XM3-CTRL
U2 U3 U4: "IC GATE DRVR HALF-BRIDGE MODULE", Case/Package=N/A, Manufacturer=WOLFSPEED

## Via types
v1: diameter 27, hole 13, Top Layer to Bottom Layer, tented both sides, 60 vias

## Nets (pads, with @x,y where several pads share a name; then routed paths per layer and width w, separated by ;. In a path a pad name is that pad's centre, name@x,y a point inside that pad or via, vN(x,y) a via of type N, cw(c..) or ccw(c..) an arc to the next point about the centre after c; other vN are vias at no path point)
+12V: J4.4 J4.5 J4.6 J17.1 J18.1 J19.1 U1.14 | length 285.5
  Top Layer w25: v1(-4840,360) -4797.82,360 U1.14@-4774.89,382.93 ; v1(-4840,390) U1.14@-4782.39,390 ; v1(-4840,420) U1.14@-4782.39,420 ; v1(-4840,450) -4797.82,450 -4774.89,427.07 U1.14@-4774.89,406.02
BLD+0: R1.1 R2.2 R9.1 R10.2 R17.1 R18.2 | length 554.5
  Top Layer w25: R17.1@-1485.75,4705 -1450,4705 R18.2@-1414.25,4705 ; R9.1@-1485.75,4875 -1450,4875 R10.2@-1414.25,4875 ; R1.1@-1485.75,5045 -1450,5045 R2.2@-1414.25,5045
  Top Layer w50: -1450,4705 -1450,4875 -1450,5045
BLD+1: R2.1 R3.2 R10.1 R11.2 R18.1 R19.2 | length 554.5
  Top Layer w25: R18.1@-1185.75,4705 -1150,4705 R19.2@-1114.25,4705 ; R10.1@-1185.75,4875 -1150,4875 R11.2@-1114.25,4875 ; R2.1@-1185.75,5045 -1150,5045 R3.2@-1114.25,5045
  Top Layer w50: -1150,4705 -1150,4875 -1150,5045
BLD+2: R3.1 R4.2 R11.1 R12.2 R19.1 R20.2 | length 554.5
  Top Layer w25: R19.1@-885.75,4705 -850,4705 R20.2@-814.25,4705 ; R11.1@-885.75,4875 -850,4875 R12.2@-814.25,4875 ; R3.1@-885.75,5045 -850,5045 R4.2@-814.25,5045
  Top Layer w50: -850,4705 -850,4875 -850,5045
BLD-0: R5.1 R6.2 R13.1 R14.2 R21.1 R22.2 | length 554.5
  Top Layer w25: R21.1@814.25,4705 850,4705 R22.2@885.75,4705 ; R13.1@814.25,4875 850,4875 R14.2@885.75,4875 ; R5.1@814.25,5045 850,5045 R6.2@885.75,5045
  Top Layer w50: 850,4705 850,4875 850,5045
BLD-1: R6.1 R7.2 R14.1 R15.2 R22.1 R23.2 | length 554.5
  Top Layer w25: R22.1@1114.25,4705 1150,4705 R23.2@1185.75,4705 ; R14.1@1114.25,4875 1150,4875 R15.2@1185.75,4875 ; R6.1@1114.25,5045 1150,5045 R7.2@1185.75,5045
  Top Layer w50: 1150,4705 1150,4875 1150,5045
BLD-2: R7.1 R8.2 R15.1 R16.2 R23.1 R24.2 | length 554.5
  Top Layer w25: R23.1@1414.25,4705 1450,4705 R24.2@1485.75,4705 ; R15.1@1414.25,4875 1450,4875 R16.2@1485.75,4875 ; R7.1@1414.25,5045 1450,5045 R8.2@1485.75,5045
  Top Layer w50: 1450,4705 1450,4875 1450,5045
DC+: C7.1A C7.1B C9.1A C9.1B C10.1A C10.1B C11.1A C11.1B C13.1A C13.1B J1.1 J5.1 J5.2 J5.3 J6.1 J6.2 J6.3 J7.1 J7.2 J7.3 Q1.DC+_1 Q1.DC+_2 Q1.DC+_3 Q1.DC+_4 Q1.DC+_5 Q1.DC+_6 Q1.DC+_7 Q1.DC+_8 Q2.DC+_1 Q2.DC+_2 Q2.DC+_3 Q2.DC+_4 Q2.DC+_5 Q2.DC+_6 Q2.DC+_7 Q2.DC+_8 Q3.DC+_1 Q3.DC+_2 Q3.DC+_3 Q3.DC+_4 Q3.DC+_5 Q3.DC+_6 Q3.DC+_7 Q3.DC+_8 R1.2 R9.2 R17.2 R25.2 R26.2 R27.2 R28.2 R29.2 R30.2 R31.2 R32.2 R33.2 R34.2 R35.2 R36.2 R37.2 R38.2 R39.2 R40.2 TP1.1 TP2.1 U1.5 U1.6 | length 514
  Top Layer w10: R17.2@-1728.11,4700 R17.2@-1714.25,4705 ; R1.2@-1728.11,5050 R1.2@-1714.25,5045
  Top Layer w25: -1775,4875 R9.2@-1714.25,4875 ; -1770,4700 R17.2@-1728.11,4700 ; -1770,5050 R1.2@-1728.11,5050 ; R17.2@-1714.25,4705 R9.2@-1714.25,4875 ; R1.2@-1714.25,5045 R9.2@-1714.25,4875
DC-: C1.2 C2.2 C3.2 C4.2 C5.2A C5.2B C6.2A C6.2B C8.2A C8.2B C12.2A C12.2B C14.2A C14.2B J3.1 Q1.DC-_1 Q1.DC-_2 Q1.DC-_3 Q1.DC-_4 Q1.DC-_5 Q1.DC-_6 Q2.DC-_1 Q2.DC-_2 Q2.DC-_3 Q2.DC-_4 Q2.DC-_5 Q2.DC-_6 Q3.DC-_1 Q3.DC-_2 Q3.DC-_3 Q3.DC-_4 Q3.DC-_5 Q3.DC-_6 R8.1 R16.1 R24.1 TP5.1 TP6.1 U1.1 U1.2 | length 2137.5
  Top Layer w10: C1.2@-4835,-2821.01 -4792.25,-2778.26 C1.2@-4725,-2778.26 -4662.75,-2778.26 C1.2@-4620,-2821.01 ; C2.2@-1685,-2821.01 -1642.25,-2778.26 C2.2@-1575,-2778.26 -1512.75,-2778.26 C2.2@-1470,-2821.01 ; C3.2@1465,-2821.01 1507.75,-2778.26 C3.2@1575,-2778.26 1637.25,-2778.26 C3.2@1680,-2821.01 ; R24.1@1714.25,4705 R24.1@1728.11,4700 ; R8.1@1714.25,5045 R8.1@1728.11,5050 ; C4.2@4615,-2821.01 4657.75,-2778.26 C4.2@4725,-2778.26 4787.25,-2778.26 C4.2@4830,-2821.01
  Top Layer w25: C1.2@-4835,-2821.01 -4835,-2857.7 -4834.12,-2858.58 v1(-4834.12,-2859.12) ; -4775,-2860 C1.2@-4775,-2821.01 ; -4670,-2860 C1.2@-4670,-2821.01 ; v1(-4620,-2860) C1.2@-4620,-2821.01 ; C2.2@-1685,-2821.01 -1685,-2857.7 -1684.12,-2858.58 v1(-1684.12,-2859.12) ; -1625,-2860 C2.2@-1625,-2821.01 ; -1520,-2860 C2.2@-1520,-2821.01 ; v1(-1470,-2860) C2.2@-1470,-2821.01 ; C3.2@1465,-2821.01 1465,-2857.7 1465.88,-2858.58 v1(1465.88,-2859.12) ; 1525,-2860 C3.2@1525,-2821.01 ; 1630,-2860 C3.2@1630,-2821.01 ; v1(1680,-2860) C3.2@1680,-2821.01 ; R24.1@1714.25,4705 R16.1@1714.25,4875 ; R8.1@1714.25,5045 R16.1@1714.25,4875 ; R24.1@1728.11,4700 1770,4700 ; R8.1@1728.11,5050 1770,5050 ; 1775,4875 R16.1@1714.25,4875 ; C4.2@4615,-2821.01 4615,-2857.7 4615.88,-2858.58 v1(4615.88,-2859.12) ; 4675,-2860 C4.2@4675,-2821.01 ; 4780,-2860 C4.2@4780,-2821.01 ; v1(4830,-2860) C4.2@4830,-2821.01
  other v1: -4795,-2860 -4760,-2860 -4725,-2860 -4690,-2860 -4655,-2860 -1645,-2860 -1610,-2860 -1575,-2860 -1540,-2860 -1505,-2860 1505,-2860 1540,-2860 1575,-2860 1610,-2860 1645,-2860 4655,-2860 4690,-2860 4725,-2860 4760,-2860 4795,-2860
G_UHS: Q3.G1 U2.2A U2.4A | length 419.1
  Top Layer w10: U2.2A@-2957.16,-1768.5 U2.2A@-2957.16,-1731 ; -2860,-1825 -2857.16,-1822.16 ; U2.4A@-2857.16,-1768.5 U2.4A@-2857.16,-1731
  Top Layer w25: -3015,-1730 U2.4A@-2870,-1730 ; U2.2A@-2957.16,-1768.5 -2907.16,-1818.5 U2.4A@-2857.16,-1768.5 ; -2845,-1823.66 U2.4A@-2845,-1770
G_ULS: Q3.G2 U2.2B U2.4B | length 419.1
  Top Layer w10: U2.2B@-2957.16,-2831.5 U2.2B@-2957.16,-2794 ; -2860,-2888 -2857.16,-2885.16 ; U2.4B@-2857.16,-2831.5 U2.4B@-2857.16,-2794
  Top Layer w25: -3015,-2793 U2.4B@-2870,-2793 ; U2.2B@-2957.16,-2831.5 -2907.16,-2881.5 U2.4B@-2857.16,-2831.5 ; -2845,-2886.66 U2.4B@-2845,-2833
G_VHS: Q2.G1 U3.2A U3.4A | length 419.1
  Top Layer w10: U3.2A@192.84,-1768.5 U3.2A@192.84,-1731 ; 290,-1825 292.84,-1822.16 ; U3.4A@292.84,-1768.5 U3.4A@292.84,-1731
  Top Layer w25: 135,-1730 U3.4A@280,-1730 ; U3.2A@192.84,-1768.5 242.84,-1818.5 U3.4A@292.84,-1768.5 ; 305,-1823.66 U3.4A@305,-1770
G_VLS: Q2.G2 U3.2B U3.4B | length 419.1
  Top Layer w10: U3.2B@192.84,-2831.5 U3.2B@192.84,-2794 ; 290,-2888 292.84,-2885.16 ; U3.4B@292.84,-2831.5 U3.4B@292.84,-2794
  Top Layer w25: 135,-2793 U3.4B@280,-2793 ; U3.2B@192.84,-2831.5 242.84,-2881.5 U3.4B@292.84,-2831.5 ; 305,-2886.66 U3.4B@305,-2833
G_WHS: Q1.G1 U4.2A U4.4A | length 419.1
  Top Layer w10: U4.2A@3342.83,-1768.5 U4.2A@3342.83,-1731 ; 3440,-1825 3442.83,-1822.16 ; U4.4A@3442.83,-1768.5 U4.4A@3442.83,-1731
  Top Layer w25: 3285,-1730 U4.4A@3430,-1730 ; U4.2A@3342.83,-1768.5 3392.83,-1818.5 U4.4A@3442.83,-1768.5 ; 3455,-1823.66 U4.4A@3455,-1770
G_WLS: Q1.G2 U4.2B U4.4B | length 419.1
  Top Layer w10: U4.2B@3342.83,-2831.5 U4.2B@3342.83,-2794 ; 3440,-2888 3442.83,-2885.16 ; U4.4B@3442.83,-2831.5 U4.4B@3442.83,-2794
  Top Layer w25: 3285,-2793 U4.4B@3430,-2793 ; U4.2B@3342.83,-2831.5 3392.83,-2881.5 U4.4B@3442.83,-2831.5 ; 3455,-2886.66 U4.4B@3455,-2833
GND: J4.1 J4.2 J4.3 J17.2 J18.2 J19.2 U1.11 | length 285.5
  Top Layer w25: v1(-5076.22,227.95) -5034.04,227.95 U1.11@-5011.11,250.88 ; v1(-5076.22,257.95) U1.11@-5018.61,257.95 ; v1(-5076.22,287.95) U1.11@-5018.61,287.95 ; v1(-5076.22,317.95) -5034.04,317.95 -5011.11,295.02 U1.11@-5011.11,273.98
MID: C5.1A C5.1B C6.1A C6.1B C7.2A C7.2B C8.1A C8.1B C9.2A C9.2B C10.2A C10.2B C11.2A C11.2B C12.1A C12.1B C13.2A C13.2B C14.1A C14.1B J2.1 R4.1 R5.2 R12.1 R13.2 R20.1 R21.2 TP3.1 TP4.1 | length 998.5
  Top Layer w10: R21.2@571.89,4700 R21.2@585.75,4705 ; R5.2@571.89,5050 R5.2@585.75,5045
  Top Layer w25: R20.1@-585.75,4705 R12.1@-585.75,4875 ; R4.1@-585.75,5045 R12.1@-585.75,4875 ; R20.1@-571.89,4700 -530,4700 ; R4.1@-571.89,5050 -530,5050 ; -525,4875 R12.1@-585.75,4875 ; 525,4875 R13.2@585.75,4875 ; 530,4700 R21.2@571.89,4700 ; 530,5050 R5.2@571.89,5050 ; R21.2@585.75,4705 R13.2@585.75,4875 ; R5.2@585.75,5045 R13.2@585.75,4875
S_UHS: Q3.S1 U2.1A U2.3A | length 541.9
  Top Layer w25: v1(-2970,-1970) -2970,-2043.16 U2.1A@-2957.16,-2056 U2.1A@-2957.16,-2047.5 ; U2.1A@-2944.66,-2095 U2.3A@-2869.66,-2095 ; v1(-2930,-1970) -2930.38,-1970.38 -2930.38,-2002.51 -2957.16,-2029.29 U2.1A@-2957.16,-2047.5 ; v1(-2890,-1970) -2890,-2002.12 U2.3A@-2862.84,-2029.29 ; v1(-2850,-1970) -2850,-2048.84 U2.3A@-2857.16,-2056 -2857.16,-2047.5 -2869.66,-2035 -2944.66,-2035 U2.1A@-2957.16,-2047.5
S_ULS: Q3.S2 U2.1B U2.3B | length 541.9
  Top Layer w25: v1(-2970,-3033) -2970,-3106.16 U2.1B@-2957.16,-3119 U2.1B@-2957.16,-3110.5 ; U2.1B@-2944.66,-3158 U2.3B@-2869.66,-3158 ; v1(-2930,-3033) -2930.38,-3033.38 -2930.38,-3065.51 -2957.16,-3092.29 U2.1B@-2957.16,-3110.5 ; v1(-2890,-3033) -2890,-3065.12 U2.3B@-2862.84,-3092.29 ; v1(-2850,-3033) -2850,-3111.84 U2.3B@-2857.16,-3119 -2857.16,-3110.5 -2869.66,-3098 -2944.66,-3098 U2.1B@-2957.16,-3110.5
S_VHS: Q2.S1 U3.1A U3.3A | length 541.9
  Top Layer w25: v1(180,-1970) 180,-2043.16 U3.1A@192.84,-2056 U3.1A@192.84,-2047.5 ; U3.1A@205.34,-2095 U3.3A@280.34,-2095 ; v1(220,-1970) 219.62,-1970.38 219.62,-2002.51 192.84,-2029.29 U3.1A@192.84,-2047.5 ; v1(260,-1970) 260,-2002.12 U3.3A@287.16,-2029.29 ; v1(300,-1970) 300,-2048.84 U3.3A@292.84,-2056 292.84,-2047.5 280.34,-2035 205.34,-2035 U3.1A@192.84,-2047.5
S_VLS: Q2.S2 U3.1B U3.3B | length 541.9
  Top Layer w25: v1(180,-3033) 180,-3106.16 U3.1B@192.84,-3119 U3.1B@192.84,-3110.5 ; U3.1B@205.34,-3158 U3.3B@280.34,-3158 ; v1(220,-3033) 219.62,-3033.38 219.62,-3065.51 192.84,-3092.29 U3.1B@192.84,-3110.5 ; v1(260,-3033) 260,-3065.12 U3.3B@287.16,-3092.29 ; v1(300,-3033) 300,-3111.84 U3.3B@292.84,-3119 292.84,-3110.5 280.34,-3098 205.34,-3098 U3.1B@192.84,-3110.5
S_WHS: Q1.S1 U4.1A U4.3A | length 541.9
  Top Layer w25: v1(3330,-1970) 3330,-2043.16 U4.1A@3342.83,-2056 U4.1A@3342.83,-2047.5 ; U4.1A@3355.33,-2095 U4.3A@3430.33,-2095 ; v1(3370,-1970) 3369.62,-1970.38 3369.62,-2002.51 3342.83,-2029.29 U4.1A@3342.83,-2047.5 ; v1(3410,-1970) 3410,-2002.12 U4.3A@3437.17,-2029.29 ; v1(3450,-1970) 3450,-2048.84 U4.3A@3442.83,-2056 3442.83,-2047.5 3430.33,-2035 3355.33,-2035 U4.1A@3342.83,-2047.5
S_WLS: Q1.S2 U4.1B U4.3B | length 541.9
  Top Layer w25: v1(3330,-3033) 3330,-3106.16 U4.1B@3342.83,-3119 U4.1B@3342.83,-3110.5 ; U4.1B@3355.33,-3158 U4.3B@3430.33,-3158 ; v1(3370,-3033) 3369.62,-3033.38 3369.62,-3065.51 3342.83,-3092.29 U4.1B@3342.83,-3110.5 ; v1(3410,-3033) 3410,-3065.12 U4.3B@3437.17,-3092.29 ; v1(3450,-3033) 3450,-3111.84 U4.3B@3442.83,-3119 3442.83,-3110.5 3430.33,-3098 3355.33,-3098 U4.1B@3342.83,-3110.5
SNB0: C1.1 R25.1 R26.1 R27.1 R28.1 | length 396
  Top Layer w10: C1.1@-4805,-2428.99 -4762.25,-2471.74 -4685.5,-2471.74 C1.1@-4642.75,-2428.99
  Top Layer w25: C1.1@-4920,-2430.67 -4920,-2379.33 ; C1.1@-4805,-2428.99 -4805,-2377.65 ; C1.1@-4642.75,-2428.99 -4642.75,-2384.66 ; C1.1@-4530,-2435.67 -4530,-2384.33
SNB1: C2.1 R29.1 R30.1 R31.1 R32.1 | length 396
  Top Layer w10: C2.1@-1655,-2428.99 -1612.25,-2471.74 -1535.5,-2471.74 C2.1@-1492.75,-2428.99
  Top Layer w25: C2.1@-1770,-2430.67 -1770,-2379.33 ; C2.1@-1655,-2428.99 -1655,-2377.65 ; C2.1@-1492.75,-2428.99 -1492.75,-2384.66 ; C2.1@-1380,-2435.67 -1380,-2384.33
SNB2: C3.1 R33.1 R34.1 R35.1 R36.1 | length 396
  Top Layer w10: C3.1@1495,-2428.99 1537.75,-2471.74 1614.5,-2471.74 C3.1@1657.25,-2428.99
  Top Layer w25: C3.1@1380,-2430.67 1380,-2379.33 ; C3.1@1495,-2428.99 1495,-2377.65 ; C3.1@1657.25,-2428.99 1657.25,-2384.66 ; C3.1@1770,-2435.67 1770,-2384.33
SNB3: C4.1 R37.1 R38.1 R39.1 R40.1 | length 396
  Top Layer w10: C4.1@4645,-2428.99 4687.75,-2471.74 4764.5,-2471.74 C4.1@4807.25,-2428.99
  Top Layer w25: C4.1@4530,-2430.67 4530,-2379.33 ; C4.1@4645,-2428.99 4645,-2377.65 ; C4.1@4807.25,-2428.99 4807.25,-2384.66 ; C4.1@4920,-2435.67 4920,-2384.33
T1U: J11.2 Q3.T1 | length 2116.6
  Layer 2 w10: J11.2@-2965,-3925 -2965,-3870 -2750,-3655 -2750,-2880 -2550,-2680 -2242.43,-2680 -2150,-2587.57 -2150,-2404.13 Q3.T1@-2205.12,-2349.02
T1V: J12.2 Q2.T1 | length 2116.6
  Layer 2 w10: J12.2@185,-3925 185,-3870 400,-3655 400,-2880 600,-2680 907.57,-2680 1000,-2587.57 1000,-2404.13 Q2.T1@944.88,-2349.02
T1W: J13.2 Q1.T1 | length 2116.6
  Layer 2 w10: J13.2@3335,-3925 3335,-3870 3550,-3655 3550,-2880 3750,-2680 4057.57,-2680 4150,-2587.57 4150,-2404.13 Q1.T1@4094.88,-2349.02
T2U: J11.1 Q3.T2 | length 1983.3
  Layer 2 w10: J11.1@-3065,-3925 -2780,-3640 -2780,-3010 -2780,-2962.57 -2780,-2887.57 -2780,-2867.57 -2562.43,-2650 -2542.43,-2650 -2260,-2650 -2205.12,-2595.12 Q3.T2@-2205.12,-2475
T2V: J12.1 Q2.T2 | length 1983.3
  Layer 2 w10: J12.1@85,-3925 370,-3640 370,-3010 370,-2962.57 370,-2887.57 370,-2867.57 587.57,-2650 607.57,-2650 890,-2650 944.88,-2595.12 Q2.T2@944.88,-2475
T2W: J13.1 Q1.T2 | length 1983.3
  Layer 2 w10: J13.1@3235,-3925 3520,-3640 3520,-3010 3520,-2962.57 3520,-2887.57 3520,-2867.57 3737.57,-2650 3757.57,-2650 4040,-2650 4094.88,-2595.12 Q1.T2@4094.88,-2475
U: J8.1 J8.2 J8.3 J14.1 Q3.AC_1 Q3.AC_2 Q3.AC_3 Q3.AC_4 Q3.AC_5 Q3.AC_6 Q3.AC_7 Q3.AC_8 TP7.1 TP8.1
V: J9.1 J9.2 J9.3 J15.1 Q2.AC_1 Q2.AC_2 Q2.AC_3 Q2.AC_4 Q2.AC_5 Q2.AC_6 Q2.AC_7 Q2.AC_8 TP9.1 TP10.1
W: J10.1 J10.2 J10.3 J16.1 Q1.AC_1 Q1.AC_2 Q1.AC_3 Q1.AC_4 Q1.AC_5 Q1.AC_6 Q1.AC_7 Q1.AC_8 TP11.1 TP12.1
pads on no net: HS1.1 HS1.2 HS1.3 HS1.4 HS1.5 HS1.6 HS1.7 HS1.8 J4. MH1.1 MH2.1 MH3.1 MH4.1 Q1. Q2. Q3.

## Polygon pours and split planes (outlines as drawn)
DC+ on Top Layer "Top Layer-DC+" (solid, pour order 537): -233.49,-1095 530,-1095 cw(c530.01,-1200.05) 635,-1196.51 635,-1903.49 ccw(c740,-1899.94) 740,-2005 2713.49,-2005 ccw(c2709.94,-1900) 2815,-1900 2815,-1200 cw(c2920.06,-1200) 2916.51,-1095 3680,-1095 cw(c3680,-1200.05) 3785,-1196.51 3785,-1903.49 ccw(c3890,-1899.94) 3890,-2005 5448.49,-2005 ccw(c5444.94,-1900.01) 5550,-1900 5550,565 5550,3448.49 ccw(c5445,3444.94) 5445,3550 4231.51,3550 ccw(c4235.06,3445) 4130.23,3451.87 4130.23,3447.33 ccw(c4235,3455.06) 4235,3350 5245,3350 cw(c5245,3244.94) 5350,3248.49 5350,835 cw(c5244.94,835) 5248.48,730 871.51,730 ccw(c875.06,625) 770,625 770,-457.02 cw(c669.95,-425.01) 673.49,-530 -665,-530 cw(c-665,-424.94) -770,-428.49 -770,628.49 ccw(c-875,624.94) -874.96,730 -4223.5,730 ccw(c-4219.94,625) -4325,625 -4325,-1095 -4530,-1095 -4530,-1265 -4933.49,-1265 ccw(c-4929.95,-1369.99) -5035,-1370 -5035,-2005 -3586.51,-2005 ccw(c-3590.06,-1900) -3485,-1900 -3485,-1200 cw(c-3379.94,-1200) -3383.49,-1095 -2620,-1095 cw(c-2619.99,-1200.05) -2515,-1196.51 -2515,-1903.49 ccw(c-2410,-1899.94) -2410,-2005 -436.51,-2005 ccw(c-440.06,-1900) -335,-1900 -335,-1200 cw(c-229.94,-1200)
+12V on Top Layer "Top Layer-+12V" (solid, pour order 415): -5549.4,-4484.91 ccw(c-5555.06,-4380) -5450,-4380 -5450,95 cw(c-5344.94,95) -5348.49,200 -4841.51,200 ccw(c-4845.06,305) -4740,305 -4740,378.49 ccw(c-4845,374.94) -4845,480 -5345,480 cw(c-5345,585.06) -5450,581.51 -5450,3544.99 -5450,3545 cw(c-5345,3545) -5345,3650 -4905,3650 ccw(c-4905,3755) -4800,3755 -4800,4345.16 ccw(c-4904.83,4345.17) -4905,4450 -5545,4450 ccw(c-5545.11,4345.11) -5650,4345 -5650,-4383.5 ccw(c-5545,-4379.94)
U on Top Layer "Top Layer-U" (solid, pour order 553): -4094.98,-5149.97 -2201.54,-5149.97 ccw(c-2205.09,-5044.98) -2100.03,-5044.97 -2100.03,-3013.61 ccw(c-2205.02,-3010.06) -2205.03,-2905 -2413.5,-2905 ccw(c-2409.94,-3010) -2515,-3010 -2515,-3670 -2615,-3770 -2615,-3940.84 cw(c-2925.28,-3964.71) -2901.43,-4275 -3076.51,-4275 cw(c-3076.51,-3936.51) -3415,-3936.51 -3415,-3770 -3485,-3700 -3485,-3006.51 ccw(c-3589.99,-3010.05) -3590,-2905 -4097.42,-2905 ccw(c-4094.92,-3010.02) -4199.97,-3010.03 -4199.97,-5041.36 ccw(c-4095.21,-5044.91) -4200.03,-5044.91 ccw(c-4094.98,-5044.92)
W on Top Layer "Top Layer-W" (solid, pour order 552): 2205.02,-5149.97 4098.46,-5149.97 ccw(c4094.91,-5044.98) 4199.97,-5044.97 4199.97,-3013.61 ccw(c4094.98,-3010.06) 4094.97,-2905 3886.5,-2905 ccw(c3890.06,-3010) 3785,-3010 3785,-3670 3685,-3770 3685,-3940.84 cw(c3374.72,-3964.71) 3398.57,-4275 3223.49,-4275 cw(c3223.49,-3936.51) 2885,-3936.51 2885,-3770 2815,-3700 2815,-3006.51 ccw(c2710.01,-3010.05) 2710,-2905 2202.58,-2905 ccw(c2205.08,-3010.02) 2100.03,-3010.03 2100.03,-5041.36 ccw(c2204.79,-5044.91) 2099.97,-5044.91 ccw(c2205.02,-5044.92)
V on Top Layer "Top Layer-V" (solid, pour order 551): -944.98,-5149.97 948.46,-5149.97 ccw(c944.91,-5044.98) 1049.97,-5044.97 1049.97,-3013.61 ccw(c944.98,-3010.06) 944.97,-2905 736.5,-2905 ccw(c740.06,-3010) 635,-3010 635,-3670 535,-3770 535,-3940.84 cw(c224.72,-3964.71) 248.57,-4275 73.49,-4275 cw(c73.49,-3936.51) -265,-3936.51 -265,-3770 -335,-3700 -335,-3006.51 ccw(c-439.99,-3010.05) -440,-2905 -947.42,-2905 ccw(c-944.92,-3010.02) -1049.97,-3010.03 -1049.97,-5041.36 ccw(c-945.21,-5044.91) -1050.03,-5044.91 ccw(c-944.98,-5044.92)
MID on Top Layer "Top Layer-MID" (solid, pour order 447): -4930,895 -715,895 cw(c-715,789.94) -610,793.49 -610,-268.49 ccw(c-505,-264.94) -505,-370 508.49,-370 ccw(c504.94,-265) 610,-265 610,790 cw(c715.06,790) 711.51,895 5083.49,895 ccw(c5079.94,1000) 5185,1000 5185,3083.49 ccw(c5080,3079.94) 5080,3185 4100,3185 4065,3185 cw(c4065,3290.06) 3960,3286.51 3960,3448.5 ccw(c3855,3444.94) 3855.85,3550 714.15,3550 cw(c715,3655.06) 610,3651.51 610,5150 -610,5150 -610,3655 cw(c-715.06,3655) -711.4,3550 -4218.38,3550 ccw(c-4214.94,3445) -4320,3445 -4320,3290 cw(c-4425.06,3290) -4421.52,3185 -4933.5,3185 ccw(c-4929.94,3080) -5035,3080 -5035,996.51 ccw(c-4930,1000.06)
DC- on Top Layer "Top Layer-DC-" (solid, pour order 441): 1240,3991.51 ccw(c1345,3995.06) 1345,3890 5448.49,3890 ccw(c5444.94,3995) 5550,3995 5550,4341.39 ccw(c5445,4344.94) 5445,4450 3100,4450 cw(c3100,4555.06) 2995,4551.51 2995,5048.49 ccw(c2890,5044.94) 2890,5150 1695,5150 1695,4480 cw(c1589.94,4480) 1593.49,4375 1341.51,4375 ccw(c1345.06,4270) 1240,4270
DC- on Top Layer "Top Layer-DC- 3" (solid, pour order 160): -2426.97,-2590 ccw(c-2426.97,-2515) -2351.97,-2515 -2351.97,-2510 ccw(c-2426.97,-2510) -2426.97,-2435 -4125,-2435 ccw(c-4125,-2510) -4200,-2510 -4200,-2515 ccw(c-4125,-2515) -4125,-2590
G_ULS on Top Layer "NONET_L02_P-001" (solid, pour order 44): -3120,-3138 ccw(c-3075,-3138) -3075,-3183 -3005,-3183 -3005,-2998 -2830,-2998 -2830,-2723 -3075,-2723 ccw(c-3075,-2768) -3120,-2768
G_UHS on Top Layer "NONET_L02_P-001" (solid, pour order 5): -3120,-2075 ccw(c-3075,-2075) -3075,-2120 -3005,-2120 -3005,-1935 -2830,-1935 -2830,-1660 -3075,-1660 ccw(c-3075,-1705) -3120,-1705
DC- on Top Layer "Top Layer-DC- 1" (solid, pour order 162): 3873.03,-2590 ccw(c3873.03,-2515) 3948.03,-2515 3948.03,-2510 ccw(c3873.03,-2510) 3873.03,-2435 2175,-2435 ccw(c2175,-2510) 2100,-2510 2100,-2515 ccw(c2175,-2515) 2175,-2590
G_WLS on Top Layer "NONET_L02_P-001" (solid, pour order 46): 3180,-3138 ccw(c3225,-3138) 3225,-3183 3295,-3183 3295,-2998 3470,-2998 3470,-2723 3225,-2723 ccw(c3225,-2768) 3180,-2768
G_WHS on Top Layer "NONET_L02_P-001" (solid, pour order 17): 3180,-2075 ccw(c3225,-2075) 3225,-2120 3295,-2120 3295,-1935 3470,-1935 3470,-1660 3225,-1660 ccw(c3225,-1705) 3180,-1705
DC- on Top Layer "Top Layer-DC- 2" (solid, pour order 161): 723.03,-2590 ccw(c723.03,-2515) 798.03,-2515 798.03,-2510 ccw(c723.03,-2510) 723.03,-2435 -975,-2435 ccw(c-975,-2510) -1050,-2510 -1050,-2515 ccw(c-975,-2515) -975,-2590
G_VLS on Top Layer "NONET_L02_P-001" (solid, pour order 45): 30,-3138 ccw(c75,-3138) 75,-3183 145,-3183 145,-2998 320,-2998 320,-2723 75,-2723 ccw(c75,-2768) 30,-2768
G_VHS on Top Layer "NONET_L02_P-001" (solid, pour order 15): 30,-2075 ccw(c75,-2075) 75,-2120 145,-2120 145,-1935 320,-1935 320,-1660 75,-1660 ccw(c75,-1705) 30,-1705
DC+ on Top Layer "Top Layer-DC+ 1" (solid, pour order 435): -1351.51,3890 ccw(c-1355.06,3995) -1250,3995 -1250,4273.49 ccw(c-1355,4269.94) -1355,4375 -1590,4375 cw(c-1590,4480.06) -1695,4476.51 -1695,5150 -2893.49,5150 ccw(c-2889.94,5045) -2995,5045 -2995,3991.51 ccw(c-2890,3995.06) -2890,3890
DC- on Top Layer "NONET_L02_P-001" (solid, pour order 82): 4520,-2735 4520,-2825 4570,-2875 4880,-2875 4930,-2825 4930,-2735
DC- on Top Layer "NONET_L02_P-001" (solid, pour order 81): 1370,-2735 1370,-2825 1420,-2875 1730,-2875 1780,-2825 1780,-2735
DC- on Top Layer "NONET_L02_P-001" (solid, pour order 80): -4930,-2735 -4930,-2825 -4880,-2875 -4570,-2875 -4520,-2825 -4520,-2735
SNB0 on Top Layer "NONET_L02_P-001" (solid, pour order 49): -5030,-2180 -5030,-2265 -4935,-2360 -4935,-2515 -4515,-2515 -4515,-2355 -4420,-2260 -4420,-2180
SNB3 on Top Layer "NONET_L02_P-001" (solid, pour order 48): 4420,-2180 4420,-2265 4515,-2360 4515,-2515 4935,-2515 4935,-2355 5030,-2260 5030,-2180
SNB2 on Top Layer "NONET_L02_P-001" (solid, pour order 47): 1270,-2180 1270,-2265 1365,-2360 1365,-2515 1785,-2515 1785,-2355 1880,-2260 1880,-2180
DC- on Top Layer "NONET_L02_P-001" (solid, pour order 34): -1780,-2735 -1780,-2825 -1730,-2875 -1420,-2875 -1370,-2825 -1370,-2735
SNB1 on Top Layer "NONET_L02_P-001" (solid, pour order 33): -1880,-2180 -1880,-2265 -1785,-2360 -1785,-2515 -1365,-2515 -1365,-2355 -1270,-2260 -1270,-2180
W on Layer 2 "Layer 2-W" (solid, pour order 569): 4199.97,-3054.88 ccw(c4096.72,-3053.25) 4199.97,-3051.62 4199.97,-3013.61 ccw(c4094.97,-3010.06) 4094.97,-2905 3886.5,-2905 ccw(c3890.06,-3010) 3785,-3010 3785,-3055 ccw(c3891.8,-3056.8) 3785,-3055 3785,-3530 cw(c3460.01,-3530.01) 3700.81,-3748.26 3595,-3935 3595,-3936.87 cw(c3329.15,-3919.15) 3311.43,-4185 3225,-4185 cw(c3225,-3935) 2975,-3935 2903.84,-3750.32 cw(c3145,-3525) 2815,-3530 2815,-3006.51 ccw(c2710,-3010.06) 2710,-2905 2202.58,-2905 ccw(c2205.08,-3010.02) 2100.03,-3010.03 2100.03,-5041.36 ccw(c2205.12,-5044.92) 2099.97,-5044.92 ccw(c2205.03,-5044.91) 2205.03,-5149.97 ccw(c2205.03,-5044.91) 2205.03,-5149.97 4098.46,-5149.97 ccw(c4094.91,-5044.97) 4199.97,-5044.97
V on Layer 2 "Layer 2-V" (solid, pour order 568): 1049.97,-3054.88 ccw(c946.72,-3053.25) 1049.97,-3051.62 1049.97,-3013.61 ccw(c944.97,-3010.06) 944.97,-2905 736.5,-2905 ccw(c740.06,-3010) 635,-3010 635,-3055 ccw(c741.8,-3056.8) 635,-3055 635,-3530 cw(c310.01,-3530.01) 550.81,-3748.26 445,-3935 445,-3936.87 cw(c179.15,-3919.15) 161.43,-4185 75,-4185 cw(c75,-3935) -175,-3935 -246.16,-3750.32 cw(c-5,-3525) -335,-3530 -335,-3006.51 ccw(c-440,-3010.06) -440,-2905 -947.42,-2905 ccw(c-944.92,-3010.02) -1049.97,-3010.03 -1049.97,-5041.36 ccw(c-944.88,-5044.92) -1050.03,-5044.92 ccw(c-944.97,-5044.91) -944.97,-5149.97 ccw(c-944.97,-5044.91) -944.97,-5149.97 948.46,-5149.97 ccw(c944.91,-5044.97) 1049.97,-5044.97
U on Layer 2 "Layer 2-U" (solid, pour order 567): -2100.03,-3054.88 ccw(c-2203.28,-3053.25) -2100.03,-3051.62 -2100.03,-3013.61 ccw(c-2205.03,-3010.06) -2205.03,-2905 -2413.5,-2905 ccw(c-2409.94,-3010) -2515,-3010 -2515,-3055 ccw(c-2408.2,-3056.8) -2515,-3055 -2515,-3530 cw(c-2839.99,-3530.01) -2599.19,-3748.26 -2705,-3935 -2705,-3936.87 cw(c-2970.85,-3919.15) -2988.57,-4185 -3075,-4185 cw(c-3075,-3935) -3325,-3935 -3396.16,-3750.32 cw(c-3155,-3525) -3485,-3530 -3485,-3006.51 ccw(c-3590,-3010.06) -3590,-2905 -4097.42,-2905 ccw(c-4094.92,-3010.02) -4199.97,-3010.03 -4199.97,-5041.36 ccw(c-4094.88,-5044.92) -4200.03,-5044.92 ccw(c-4094.97,-5044.91) -4094.97,-5149.97 ccw(c-4094.97,-5044.91) -4094.97,-5149.97 -2201.54,-5149.97 ccw(c-2205.09,-5044.97) -2100.03,-5044.97
DC+ on Layer 2 "Layer 2-DC+" (solid, pour order 529): 3815,-2005 5448.49,-2005 ccw(c5444.94,-1900) 5550,-1900 5550,3748.49 ccw(c5445,3744.94) 5445.2,3850 -545,3850 cw(c-545,3955.06) -650,3951.51 -650,5048.49 ccw(c-755,5044.94) -755,5150 -2893.49,5150 ccw(c-2889.94,5045) -2995,5045 -2995,3955 cw(c-3100.06,3955) -3096.51,3850 -4268.49,3850 ccw(c-4264.94,3745) -4370,3745 -4370,3325 cw(c-4475.06,3325) -4471.51,3220 -4933.49,3220 ccw(c-4929.94,3115) -5035,3115 -5035,995 ccw(c-4935,995) -4935,895 -4855,895 cw(c-4855,465) -4425,465 -4425,215 cw(c-4855,215) -4855,-215 -4935,-215 ccw(c-4935,-315) -5035,-315 -5035,-1903.49 ccw(c-4930,-1899.94) -4930,-2005 -3446.51,-2005 ccw(c-3450.06,-1900) -3345,-1900 -3345,-1435 -2815,-1435 -2815,-1675 -2485,-2005 -296.51,-2005 ccw(c-300.06,-1900) -195,-1900 -195,-1435 335,-1435 335,-1675 665,-2005 2853.49,-2005 ccw(c2849.94,-1900) 2955,-1900 2955,-1435 3485,-1435 3485,-1675
MID on Layer 2 "Layer 2-MID" (solid, pour order 517): -490,4180 ccw(c-378.11,4181.89) -380,4070 385,4070 ccw(c383.19,4176.81) 490,4175 490,5048.49 ccw(c385,5044.94) 385,5150 -388.49,5150 ccw(c-384.94,5045) -490,5045
DC- on Layer 2 "Layer 2-DC-" (solid, pour order 489): 1345,4070 5448.49,4070 ccw(c5444.94,4175) 5550,4175 5550,4341.39 ccw(c5445,4344.94) 5445,4450 3100,4450 cw(c3100,4555.06) 2995,4551.51 2995,5048.49 ccw(c2890,5044.94) 2890,5150 1796.51,5150 ccw(c1800.06,5045) 1695,5045 1695,4480 cw(c1589.95,4479.99) 1593.49,4375 1341.51,4375 ccw(c1345.06,4270) 1240,4270 1240,4171.51 ccw(c1345,4175.06)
